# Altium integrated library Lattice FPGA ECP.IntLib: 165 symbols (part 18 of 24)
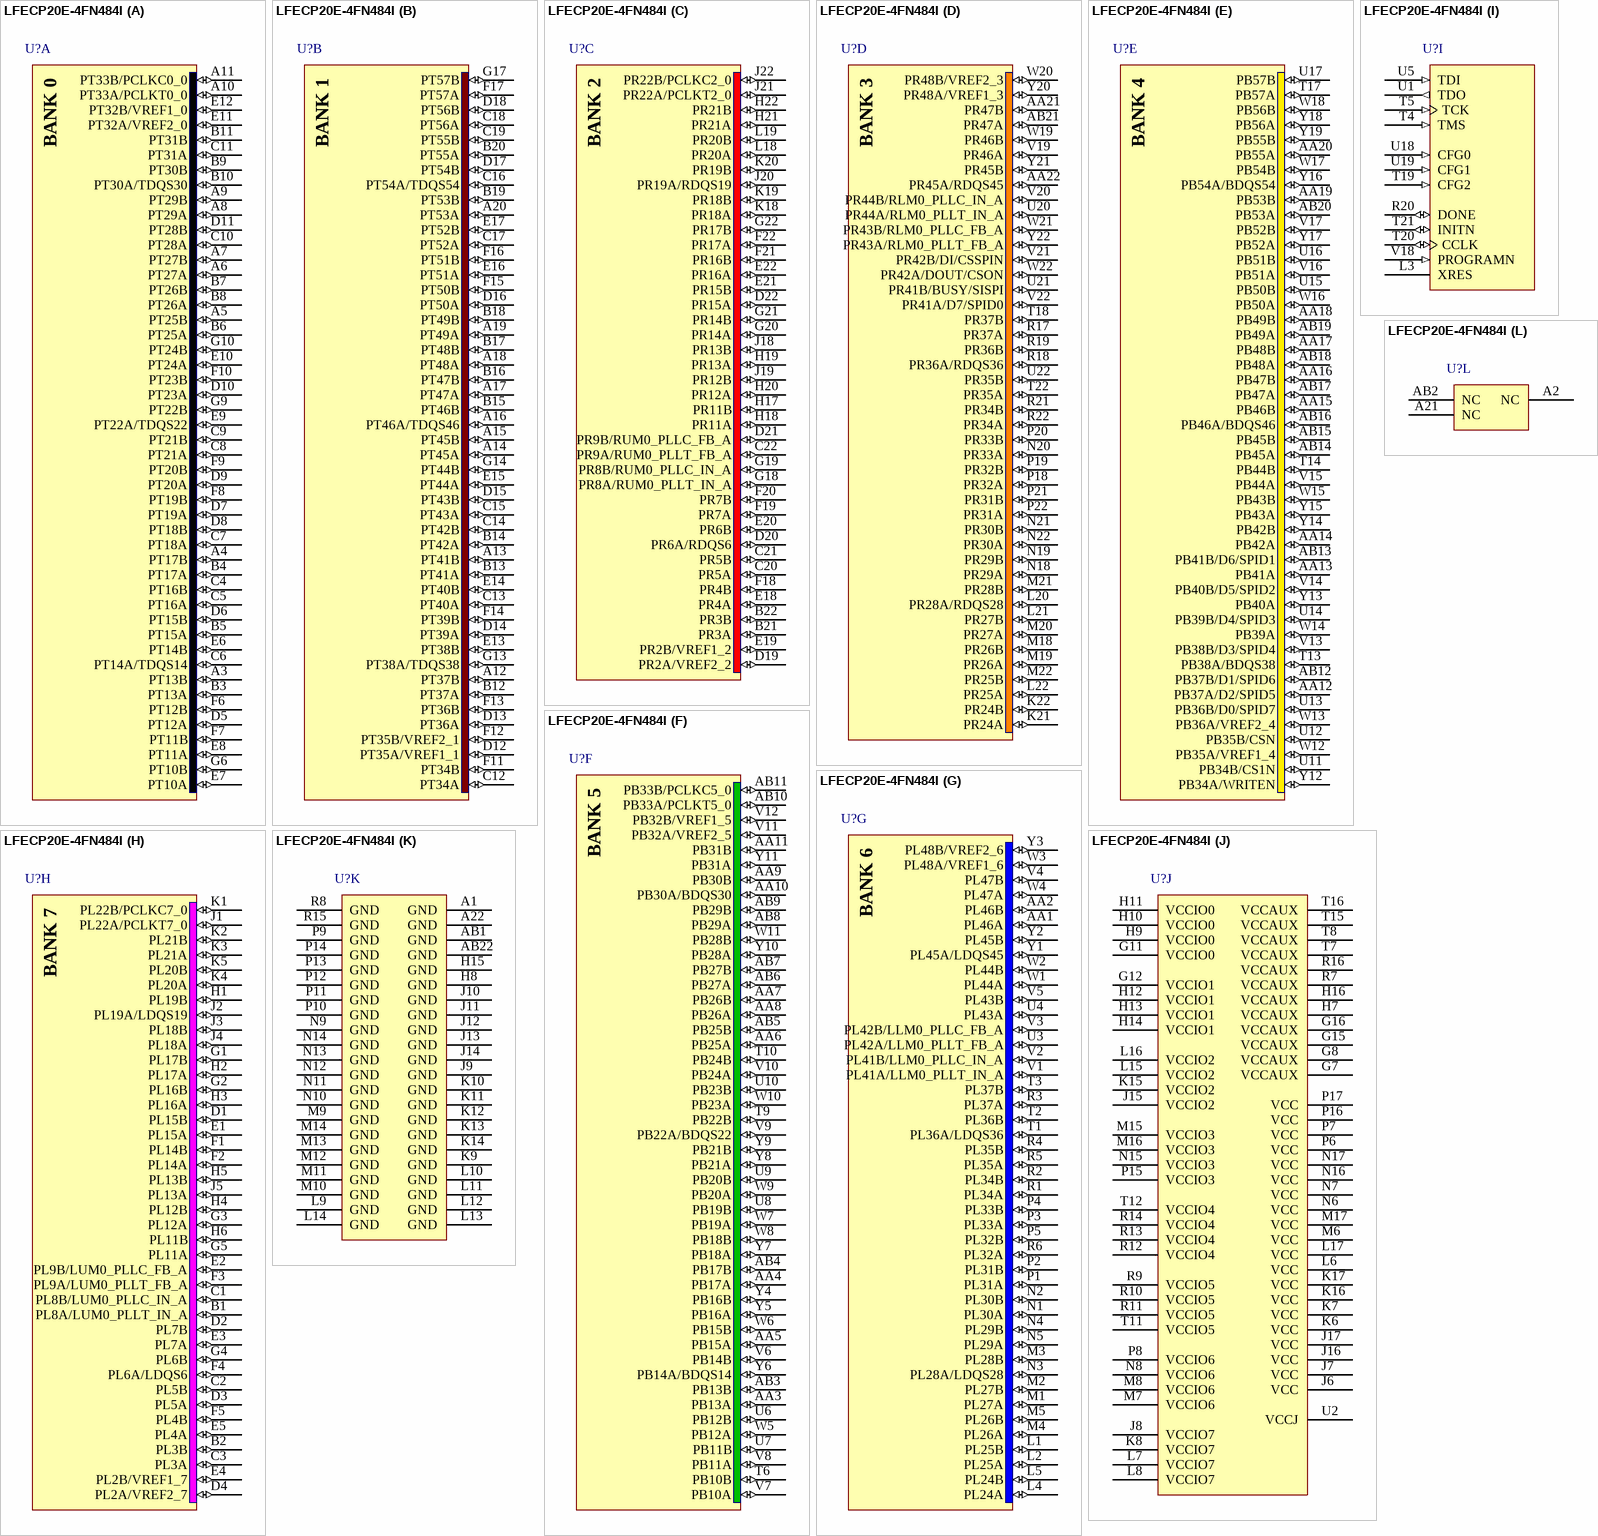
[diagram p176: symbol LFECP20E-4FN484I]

## LFECP20E-4FN484I
designator U?
ECP 1.2V FPGA, 360 I/Os, 4 PLLs, 19.7K LUTs, 7 sysDSP Blocks, 28 18x18 Multipliers, 484-Pin fpBGA, Pb-Free, Speed Grade 4, Industrial Temperature Grade; Note: Pins J6, J17, P6 and P17 are tied to VCCPLL.
footprint fpBGA484 (BGA, 484-Leads, Body 23x23mm, Pitch 1mm)
3D model ECP20E-fpBGA484 (484-Ball Fine Pitch Ball Grid Array (fpBGA484))
part A pins: A3 PT13B (io), A4 PT17B (io), A5 PT25B (io), A6 PT27A (io), A7 PT27B (io), A8 PT29A (io), A9 PT29B (io), A10 PT33A/PCLKT0_0 (io), A11 PT33B/PCLKC0_0 (io), B3 PT13A (io), B4 PT17A (io), B5 PT15A (io), B6 PT25A (io), B7 PT26B (io), B8 PT26A (io), B9 PT30B (io), B10 PT30A/TDQS30 (io), B11 PT31B (io), C4 PT16B (io), C5 PT16A (io), C6 PT14A/TDQS14 (io), C7 PT18A (io), C8 PT21A (io), C9 PT21B (io), C10 PT28A (io), C11 PT31A (io), D5 PT12A (io), D6 PT15B (io), D7 PT19A (io), D8 PT18B (io), D9 PT20A (io), D10 PT23A (io), D11 PT28B (io), E6 PT14B (io), E7 PT10A (io), E8 PT11A (io), E9 PT22A/TDQS22 (io), E10 PT24A (io), E11 PT32A/VREF2_0 (io), E12 PT32B/VREF1_0 (io), F6 PT12B (io), F7 PT11B (io), F8 PT19B (io), F9 PT20B (io), F10 PT23B (io), G6 PT10B (io), G9 PT22B (io), G10 PT24B (io)
part B pins: A12 PT37B (io), A13 PT41B (io), A14 PT45A (io), A15 PT45B (io), A16 PT46A/TDQS46 (io), A17 PT47A (io), A18 PT48A (io), A19 PT49A (io), A20 PT53A (io), B12 PT37A (io), B13 PT41A (io), B14 PT42A (io), B15 PT46B (io), B16 PT47B (io), B17 PT48B (io), B18 PT49B (io), B19 PT53B (io), B20 PT55A (io), C12 PT34A (io), C13 PT40A (io), C14 PT42B (io), C15 PT43A (io), C16 PT54A/TDQS54 (io), C17 PT52A (io), C18 PT56A (io), C19 PT55B (io), D12 PT35A/VREF1_1 (io), D13 PT36A (io), D14 PT39A (io), D15 PT43B (io), D16 PT50A (io), D17 PT54B (io), D18 PT56B (io), E13 PT38B (io), E14 PT40B (io), E15 PT44A (io), E16 PT51A (io), E17 PT52B (io), F11 PT34B (io), F12 PT35B/VREF2_1 (io), F13 PT36B (io), F14 PT39B (io), F15 PT50B (io), F16 PT51B (io), F17 PT57A (io), G13 PT38A/TDQS38 (io), G14 PT44B (io), G17 PT57B (io)
part C pins: B21 PR3A (io), B22 PR3B (io), C20 PR5A (io), C21 PR5B (io), C22 PR9A/RUM0_PLLT_FB_A (io), D19 PR2A/VREF2_2 (io), D20 PR6A/RDQS6 (io), D21 PR9B/RUM0_PLLC_FB_A (io), D22 PR15A (io), E18 PR4A (io), E19 PR2B/VREF1_2 (io), E20 PR6B (io), E21 PR15B (io), E22 PR16A (io), F18 PR4B (io), F19 PR7A (io), F20 PR7B (io), F21 PR16B (io), F22 PR17A (io), G18 PR8A/RUM0_PLLT_IN_A (io), G19 PR8B/RUM0_PLLC_IN_A (io), G20 PR14A (io), G21 PR14B (io), G22 PR17B (io), H17 PR11B (io), H18 PR11A (io), H19 PR13A (io), H20 PR12A (io), H21 PR21A (io), H22 PR21B (io), J18 PR13B (io), J19 PR12B (io), J20 PR19A/RDQS19 (io), J21 PR22A/PCLKT2_0 (io), J22 PR22B/PCLKC2_0 (io), K18 PR18A (io), K19 PR18B (io), K20 PR19B (io), L18 PR20A (io), L19 PR20B (io)
part D pins: AA21 PR47B (io), AA22 PR45A/RDQS45 (io), AB21 PR47A (io), K21 PR24A (io), K22 PR24B (io), L20 PR28A/RDQS28 (io), L21 PR27B (io), L22 PR25A (io), M18 PR26B (io), M19 PR26A (io), M20 PR27A (io), M21 PR28B (io), M22 PR25B (io), N18 PR29A (io), N19 PR29B (io), N20 PR33A (io), N21 PR30B (io), N22 PR30A (io), P18 PR32A (io), P19 PR32B (io), P20 PR33B (io), P21 PR31B (io), P22 PR31A (io), R17 PR37A (io), R18 PR36A/RDQS36 (io), R19 PR36B (io), R21 PR34B (io), R22 PR34A (io), T18 PR37B (io), T22 PR35A (io), U20 PR44A/RLM0_PLLT_IN_A (io), U21 PR41B/BUSY/SISPI (io), U22 PR35B (io), V19 PR46A (io), V20 PR44B/RLM0_PLLC_IN_A (io), V21 PR42B/DI/CSSPIN (io), V22 PR41A/D7/SPID0 (io), W19 PR46B (io), W20 PR48B/VREF2_3 (io), W21 PR43B/RLM0_PLLC_FB_A (io), W22 PR42A/DOUT/CSON (io), Y20 PR48A/VREF1_3 (io), Y21 PR45B (io), Y22 PR43A/RLM0_PLLT_FB_A (io)
part E pins: AA12 PB37A/D2/SPID5 (io), AA13 PB41A (io), AA14 PB42A (io), AA15 PB46B (io), AA16 PB47B (io), AA17 PB48B (io), AA18 PB49B (io), AA19 PB53B (io), AA20 PB55A (io), AB12 PB37B/D1/SPID6 (io), AB13 PB41B/D6/SPID1 (io), AB14 PB45A (io), AB15 PB45B (io), AB16 PB46A/BDQS46 (io), AB17 PB47A (io), AB18 PB48A (io), AB19 PB49A (io), AB20 PB53A (io), T13 PB38A/BDQS38 (io), T14 PB44B (io), T17 PB57A (io), U11 PB34B/CS1N (io), U12 PB35B/CSN (io), U13 PB36B/D0/SPID7 (io), U14 PB39B/D4/SPID3 (io), U15 PB50B (io), U16 PB51B (io), U17 PB57B (io), V13 PB38B/D3/SPID4 (io), V14 PB40B/D5/SPID2 (io), V15 PB44A (io), V16 PB51A (io), V17 PB52B (io), W12 PB35A/VREF1_4 (io), W13 PB36A/VREF2_4 (io), W14 PB39A (io), W15 PB43B (io), W16 PB50A (io), W17 PB54B (io), W18 PB56B (io), Y12 PB34A/WRITEN (io), Y13 PB40A (io), Y14 PB42B (io), Y15 PB43A (io), Y16 PB54A/BDQS54 (io), Y17 PB52A (io), Y18 PB56A (io), Y19 PB55B (io)
part F pins: AA3 PB13A (io), AA4 PB17A (io), AA5 PB15A (io), AA6 PB25A (io), AA7 PB26B (io), AA8 PB26A (io), AA9 PB30B (io), AA10 PB30A/BDQS30 (io), AA11 PB31B (io), AB3 PB13B (io), AB4 PB17B (io), AB5 PB25B (io), AB6 PB27A (io), AB7 PB27B (io), AB8 PB29A (io), AB9 PB29B (io), AB10 PB33A/PCLKT5_0 (io), AB11 PB33B/PCLKC5_0 (io), T6 PB10B (io), T9 PB22B (io), T10 PB24B (io), U6 PB12B (io), U7 PB11B (io), U8 PB19B (io), U9 PB20B (io), U10 PB23B (io), V6 PB14B (io), V7 PB10A (io), V8 PB11A (io), V9 PB22A/BDQS22 (io), V10 PB24A (io), V11 PB32A/VREF2_5 (io), V12 PB32B/VREF1_5 (io), W5 PB12A (io), W6 PB15B (io), W7 PB19A (io), W8 PB18B (io), W9 PB20A (io), W10 PB23A (io), W11 PB28B (io), Y4 PB16B (io), Y5 PB16A (io), Y6 PB14A/BDQS14 (io), Y7 PB18A (io), Y8 PB21A (io), Y9 PB21B (io), Y10 PB28A (io), Y11 PB31A (io)
part G pins: AA1 PL46A (io), AA2 PL46B (io), L1 PL25B (io), L2 PL25A (io), L4 PL24A (io), L5 PL24B (io), M1 PL27A (io), M2 PL27B (io), M3 PL28B (io), M4 PL26A (io), M5 PL26B (io), N1 PL30A (io), N2 PL30B (io), N3 PL28A/LDQS28 (io), N4 PL29B (io), N5 PL29A (io), P1 PL31A (io), P2 PL31B (io), P3 PL33A (io), P4 PL33B (io), P5 PL32B (io), R1 PL34A (io), R2 PL34B (io), R3 PL37A (io), R4 PL35B (io), R5 PL35A (io), R6 PL32A (io), T1 PL36A/LDQS36 (io), T2 PL36B (io), T3 PL37B (io), U3 PL42A/LLM0_PLLT_FB_A (io), U4 PL43A (io), V1 PL41A/LLM0_PLLT_IN_A (io), V2 PL41B/LLM0_PLLC_IN_A (io), V3 PL42B/LLM0_PLLC_FB_A (io), V4 PL47B (io), V5 PL43B (io), W1 PL44A (io), W2 PL44B (io), W3 PL48A/VREF1_6 (io), W4 PL47A (io), Y1 PL45A/LDQS45 (io), Y2 PL45B (io), Y3 PL48B/VREF2_6 (io)
part H pins: B1 PL8A/LUM0_PLLT_IN_A (io), B2 PL3B (io), C1 PL8B/LUM0_PLLC_IN_A (io), C2 PL5B (io), C3 PL3A (io), D1 PL15B (io), D2 PL7B (io), D3 PL5A (io), D4 PL2A/VREF2_7 (io), E1 PL15A (io), E2 PL9B/LUM0_PLLC_FB_A (io), E3 PL7A (io), E4 PL2B/VREF1_7 (io), E5 PL4A (io), F1 PL14B (io), F2 PL14A (io), F3 PL9A/LUM0_PLLT_FB_A (io), F4 PL6A/LDQS6 (io), F5 PL4B (io), G1 PL17B (io), G2 PL16B (io), G3 PL12A (io), G4 PL6B (io), G5 PL11A (io), H1 PL19B (io), H2 PL17A (io), H3 PL16A (io), H4 PL12B (io), H5 PL13B (io), H6 PL11B (io), J1 PL22A/PCLKT7_0 (io), J2 PL19A/LDQS19 (io), J3 PL18B (io), J4 PL18A (io), J5 PL13A (io), K1 PL22B/PCLKC7_0 (io), K2 PL21B (io), K3 PL21A (io), K4 PL20A (io), K5 PL20B (io)
part I pins: L3 XRES, R20 DONE (io), T4 TMS (in), T5 TCK (in), T19 CFG2 (in), T20 CCLK (io), T21 INITN (io), U1 TDO (out), U5 TDI (in), U18 CFG0 (in), U19 CFG1 (in), V18 PROGRAMN (in)
part J pins: G7 VCCAUX (power), G8 VCCAUX (power), G11 VCCIO0 (power), G12 VCCIO1 (power), G15 VCCAUX (power), G16 VCCAUX (power), H7 VCCAUX (power), H9 VCCIO0 (power), H10 VCCIO0 (power), H11 VCCIO0 (power), H12 VCCIO1 (power), H13 VCCIO1 (power), H14 VCCIO1 (power), H16 VCCAUX (power), J6 VCC (power), J7 VCC (power), J8 VCCIO7 (power), J15 VCCIO2 (power), J16 VCC (power), J17 VCC (power), K6 VCC (power), K7 VCC (power), K8 VCCIO7 (power), K15 VCCIO2 (power), K16 VCC (power), K17 VCC (power), L6 VCC (power), L7 VCCIO7 (power), L8 VCCIO7 (power), L15 VCCIO2 (power), L16 VCCIO2 (power), L17 VCC (power), M6 VCC (power), M7 VCCIO6 (power), M8 VCCIO6 (power), M15 VCCIO3 (power), M16 VCCIO3 (power), M17 VCC (power), N6 VCC (power), N7 VCC (power), N8 VCCIO6 (power), N15 VCCIO3 (power), N16 VCC (power), N17 VCC (power), P6 VCC (power), P7 VCC (power), P8 VCCIO6 (power), P15 VCCIO3 (power), P16 VCC (power), P17 VCC (power), R7 VCCAUX (power), R9 VCCIO5 (power), R10 VCCIO5 (power), R11 VCCIO5 (power), R12 VCCIO4 (power), R13 VCCIO4 (power), R14 VCCIO4 (power), R16 VCCAUX (power), T7 VCCAUX (power), T8 VCCAUX (power), T11 VCCIO5 (power), T12 VCCIO4 (power), T15 VCCAUX (power), T16 VCCAUX (power), U2 VCCJ (power)
part K pins: A1 GND (power), A22 GND (power), AB1 GND (power), AB22 GND (power), H8 GND (power), H15 GND (power), J9 GND (power), J10 GND (power), J11 GND (power), J12 GND (power), J13 GND (power), J14 GND (power), K9 GND (power), K10 GND (power), K11 GND (power), K12 GND (power), K13 GND (power), K14 GND (power), L9 GND (power), L10 GND (power), L11 GND (power), L12 GND (power), L13 GND (power), L14 GND (power), M9 GND (power), M10 GND (power), M11 GND (power), M12 GND (power), M13 GND (power), M14 GND (power), N9 GND (power), N10 GND (power), N11 GND (power), N12 GND (power), N13 GND (power), N14 GND (power), P9 GND (power), P10 GND (power), P11 GND (power), P12 GND (power), P13 GND (power), P14 GND (power), R8 GND (power), R15 GND (power)
part L pins: A2 NC, A21 NC, AB2 NC

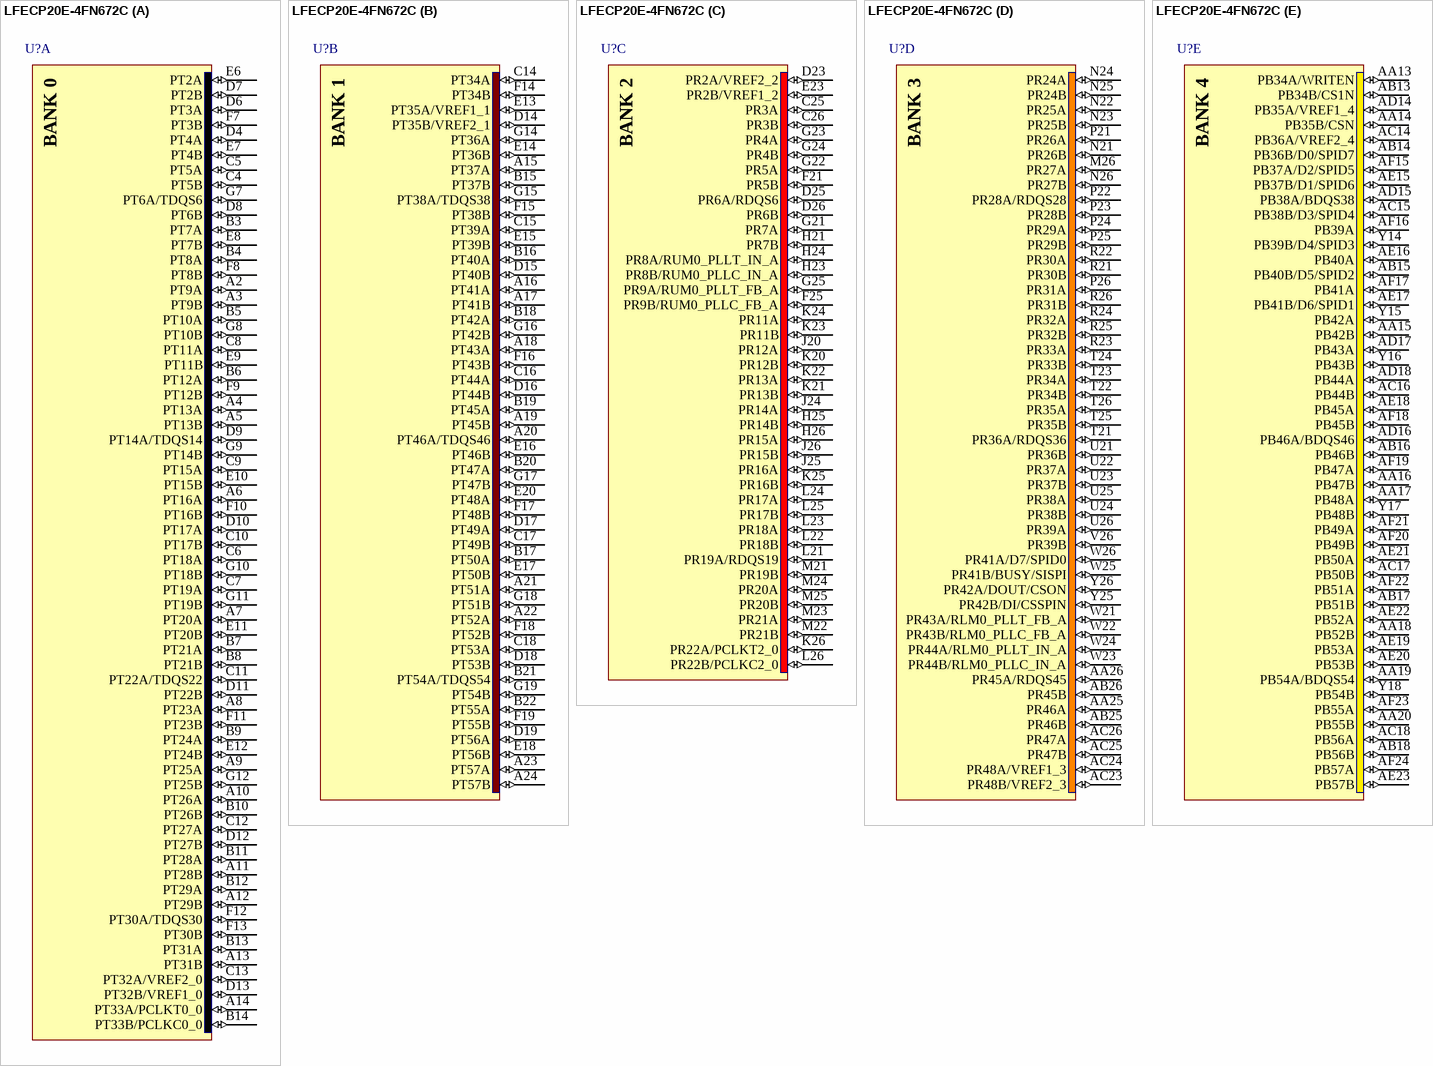
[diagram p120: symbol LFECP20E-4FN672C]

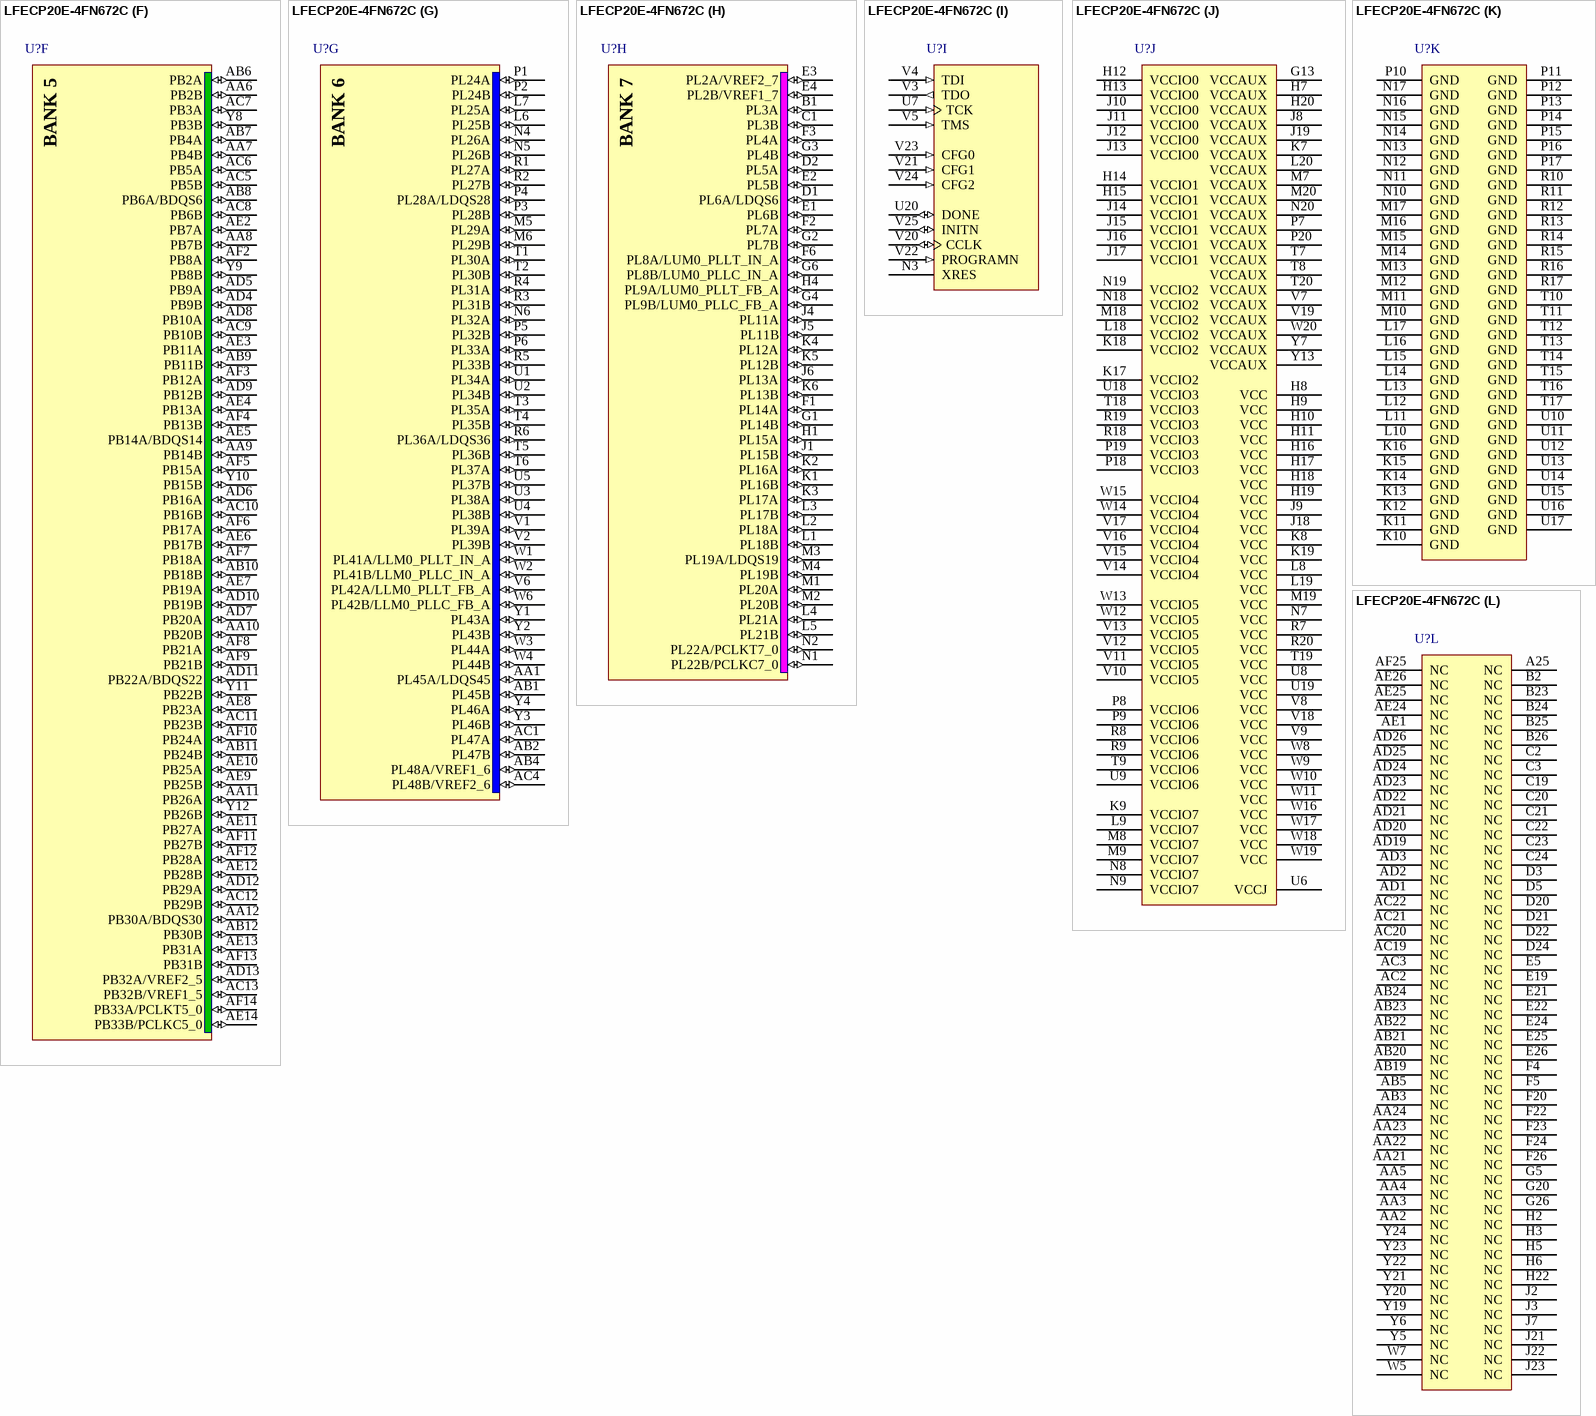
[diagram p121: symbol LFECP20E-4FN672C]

## LFECP20E-4FN672C
designator U?
ECP 1.2V FPGA, 400 I/Os, 4 PLLs, 19.7K LUTs, 7 sysDSP Blocks, 28 18x18 Multipliers, 672-Pin fpBGA, Pb-Free, Speed Grade 4, Commercial Temperature Grade; Note: Pins K19, L8, U8 and U19 are tied to VCCPLL.
footprint fpBGA672 (BGA, 672-Leads, Body 27x27mm, Pitch 1mm)
3D model ECP20E-fpBGA672 (672-Ball Fine Pitch Ball Grid Array (fpBGA672))
part A pins: A2 PT9A (io), A3 PT9B (io), A4 PT13A (io), A5 PT13B (io), A6 PT16A (io), A7 PT20A (io), A8 PT23A (io), A9 PT25A (io), A10 PT26A (io), A11 PT28B (io), A12 PT29B (io), A13 PT31B (io), A14 PT33A/PCLKT0_0 (io), B3 PT7A (io), B4 PT8A (io), B5 PT10A (io), B6 PT12A (io), B7 PT21A (io), B8 PT21B (io), B9 PT24A (io), B10 PT26B (io), B11 PT28A (io), B12 PT29A (io), B13 PT31A (io), B14 PT33B/PCLKC0_0 (io), C4 PT5B (io), C5 PT5A (io), C6 PT18A (io), C7 PT19A (io), C8 PT11A (io), C9 PT15A (io), C10 PT17B (io), C11 PT22A/TDQS22 (io), C12 PT27A (io), C13 PT32A/VREF2_0 (io), D4 PT4A (io), D6 PT3A (io), D7 PT2B (io), D8 PT6B (io), D9 PT14A/TDQS14 (io), D10 PT17A (io), D11 PT22B (io), D12 PT27B (io), D13 PT32B/VREF1_0 (io), E6 PT2A (io), E7 PT4B (io), E8 PT7B (io), E9 PT11B (io), E10 PT15B (io), E11 PT20B (io), E12 PT24B (io), F7 PT3B (io), F8 PT8B (io), F9 PT12B (io), F10 PT16B (io), F11 PT23B (io), F12 PT30A/TDQS30 (io), F13 PT30B (io), G7 PT6A/TDQS6 (io), G8 PT10B (io), G9 PT14B (io), G10 PT18B (io), G11 PT19B (io), G12 PT25B (io)
part B pins: A15 PT37A (io), A16 PT41A (io), A17 PT41B (io), A18 PT43A (io), A19 PT45B (io), A20 PT46A/TDQS46 (io), A21 PT51A (io), A22 PT52A (io), A23 PT57A (io), A24 PT57B (io), B15 PT37B (io), B16 PT40A (io), B17 PT50A (io), B18 PT42A (io), B19 PT45A (io), B20 PT47A (io), B21 PT54A/TDQS54 (io), B22 PT55A (io), C14 PT34A (io), C15 PT39A (io), C16 PT44A (io), C17 PT49B (io), C18 PT53A (io), D14 PT35B/VREF2_1 (io), D15 PT40B (io), D16 PT44B (io), D17 PT49A (io), D18 PT53B (io), D19 PT56A (io), E13 PT35A/VREF1_1 (io), E14 PT36B (io), E15 PT39B (io), E16 PT46B (io), E17 PT50B (io), E18 PT56B (io), E20 PT48A (io), F14 PT34B (io), F15 PT38B (io), F16 PT43B (io), F17 PT48B (io), F18 PT52B (io), F19 PT55B (io), G14 PT36A (io), G15 PT38A/TDQS38 (io), G16 PT42B (io), G17 PT47B (io), G18 PT51B (io), G19 PT54B (io)
part C pins: C25 PR3A (io), C26 PR3B (io), D23 PR2A/VREF2_2 (io), D25 PR6A/RDQS6 (io), D26 PR6B (io), E23 PR2B/VREF1_2 (io), F21 PR5B (io), F25 PR9B/RUM0_PLLC_FB_A (io), G21 PR7A (io), G22 PR5A (io), G23 PR4A (io), G24 PR4B (io), G25 PR9A/RUM0_PLLT_FB_A (io), H21 PR7B (io), H23 PR8B/RUM0_PLLC_IN_A (io), H24 PR8A/RUM0_PLLT_IN_A (io), H25 PR14B (io), H26 PR15A (io), J20 PR12A (io), J24 PR14A (io), J25 PR16A (io), J26 PR15B (io), K20 PR12B (io), K21 PR13B (io), K22 PR13A (io), K23 PR11B (io), K24 PR11A (io), K25 PR16B (io), K26 PR22A/PCLKT2_0 (io), L21 PR19A/RDQS19 (io), L22 PR18B (io), L23 PR18A (io), L24 PR17A (io), L25 PR17B (io), L26 PR22B/PCLKC2_0 (io), M21 PR19B (io), M22 PR21B (io), M23 PR21A (io), M24 PR20A (io), M25 PR20B (io)
part D pins: AA25 PR46A (io), AA26 PR45A/RDQS45 (io), AB25 PR46B (io), AB26 PR45B (io), AC23 PR48B/VREF2_3 (io), AC24 PR48A/VREF1_3 (io), AC25 PR47B (io), AC26 PR47A (io), M26 PR27A (io), N21 PR26B (io), N22 PR25A (io), N23 PR25B (io), N24 PR24A (io), N25 PR24B (io), N26 PR27B (io), P21 PR26A (io), P22 PR28A/RDQS28 (io), P23 PR28B (io), P24 PR29A (io), P25 PR29B (io), P26 PR31A (io), R21 PR30B (io), R22 PR30A (io), R23 PR33A (io), R24 PR32A (io), R25 PR32B (io), R26 PR31B (io), T21 PR36A/RDQS36 (io), T22 PR34B (io), T23 PR34A (io), T24 PR33B (io), T25 PR35B (io), T26 PR35A (io), U21 PR36B (io), U22 PR37A (io), U23 PR37B (io), U24 PR38B (io), U25 PR38A (io), U26 PR39A (io), V26 PR39B (io), W21 PR43A/RLM0_PLLT_FB_A (io), W22 PR43B/RLM0_PLLC_FB_A (io), W23 PR44B/RLM0_PLLC_IN_A (io), W24 PR44A/RLM0_PLLT_IN_A (io), W25 PR41B/BUSY/SISPI (io), W26 PR41A/D7/SPID0 (io), Y25 PR42B/DI/CSSPIN (io), Y26 PR42A/DOUT/CSON (io)
part E pins: AA13 PB34A/WRITEN (io), AA14 PB35B/CSN (io), AA15 PB42B (io), AA16 PB47B (io), AA17 PB48A (io), AA18 PB52B (io), AA19 PB54A/BDQS54 (io), AA20 PB55B (io), AB13 PB34B/CS1N (io), AB14 PB36B/D0/SPID7 (io), AB15 PB40B/D5/SPID2 (io), AB16 PB46B (io), AB17 PB51B (io), AB18 PB56B (io), AC14 PB36A/VREF2_4 (io), AC15 PB38B/D3/SPID4 (io), AC16 PB44B (io), AC17 PB50B (io), AC18 PB56A (io), AD14 PB35A/VREF1_4 (io), AD15 PB38A/BDQS38 (io), AD16 PB46A/BDQS46 (io), AD17 PB43A (io), AD18 PB44A (io), AE15 PB37B/D1/SPID6 (io), AE16 PB40A (io), AE17 PB41B/D6/SPID1 (io), AE18 PB45A (io), AE19 PB53A (io), AE20 PB53B (io), AE21 PB50A (io), AE22 PB52A (io), AE23 PB57B (io), AF15 PB37A/D2/SPID5 (io), AF16 PB39A (io), AF17 PB41A (io), AF18 PB45B (io), AF19 PB47A (io), AF20 PB49B (io), AF21 PB49A (io), AF22 PB51A (io), AF23 PB55A (io), AF24 PB57A (io), Y14 PB39B/D4/SPID3 (io), Y15 PB42A (io), Y16 PB43B (io), Y17 PB48B (io), Y18 PB54B (io)
part F pins: AA6 PB2B (io), AA7 PB4B (io), AA8 PB7B (io), AA9 PB14B (io), AA10 PB20B (io), AA11 PB26A (io), AA12 PB30A/BDQS30 (io), AB6 PB2A (io), AB7 PB4A (io), AB8 PB6A/BDQS6 (io), AB9 PB11B (io), AB10 PB18B (io), AB11 PB24B (io), AB12 PB30B (io), AC5 PB5B (io), AC6 PB5A (io), AC7 PB3A (io), AC8 PB6B (io), AC9 PB10B (io), AC10 PB16B (io), AC11 PB23B (io), AC12 PB29B (io), AC13 PB32B/VREF1_5 (io), AD4 PB9B (io), AD5 PB9A (io), AD6 PB16A (io), AD7 PB20A (io), AD8 PB10A (io), AD9 PB12B (io), AD10 PB19B (io), AD11 PB22A/BDQS22 (io), AD12 PB29A (io), AD13 PB32A/VREF2_5 (io), AE2 PB7A (io), AE3 PB11A (io), AE4 PB13A (io), AE5 PB14A/BDQS14 (io), AE6 PB17B (io), AE7 PB19A (io), AE8 PB23A (io), AE9 PB25B (io), AE10 PB25A (io), AE11 PB27A (io), AE12 PB28B (io), AE13 PB31A (io), AE14 PB33B/PCLKC5_0 (io), AF2 PB8A (io), AF3 PB12A (io), AF4 PB13B (io), AF5 PB15A (io), AF6 PB17A (io), AF7 PB18A (io), AF8 PB21A (io), AF9 PB21B (io), AF10 PB24A (io), AF11 PB27B (io), AF12 PB28A (io), AF13 PB31B (io), AF14 PB33A/PCLKT5_0 (io), Y8 PB3B (io), Y9 PB8B (io), Y10 PB15B (io), Y11 PB22B (io), Y12 PB26B (io)
part G pins: AA1 PL45A/LDQS45 (io), AB1 PL45B (io), AB2 PL47B (io), AB4 PL48A/VREF1_6 (io), AC1 PL47A (io), AC4 PL48B/VREF2_6 (io), L6 PL25B (io), L7 PL25A (io), M5 PL29A (io), M6 PL29B (io), N4 PL26A (io), N5 PL26B (io), N6 PL32A (io), P1 PL24A (io), P2 PL24B (io), P3 PL28B (io), P4 PL28A/LDQS28 (io), P5 PL32B (io), P6 PL33A (io), R1 PL27A (io), R2 PL27B (io), R3 PL31B (io), R4 PL31A (io), R5 PL33B (io), R6 PL36A/LDQS36 (io), T1 PL30A (io), T2 PL30B (io), T3 PL35A (io), T4 PL35B (io), T5 PL36B (io), T6 PL37A (io), U1 PL34A (io), U2 PL34B (io), U3 PL38A (io), U4 PL38B (io), U5 PL37B (io), V1 PL39A (io), V2 PL39B (io), V6 PL42A/LLM0_PLLT_FB_A (io), W1 PL41A/LLM0_PLLT_IN_A (io), W2 PL41B/LLM0_PLLC_IN_A (io), W3 PL44A (io), W4 PL44B (io), W6 PL42B/LLM0_PLLC_FB_A (io), Y1 PL43A (io), Y2 PL43B (io), Y3 PL46B (io), Y4 PL46A (io)
part H pins: B1 PL3A (io), C1 PL3B (io), D1 PL6A/LDQS6 (io), D2 PL5A (io), E1 PL6B (io), E2 PL5B (io), E3 PL2A/VREF2_7 (io), E4 PL2B/VREF1_7 (io), F1 PL14A (io), F2 PL7A (io), F3 PL4A (io), F6 PL8A/LUM0_PLLT_IN_A (io), G1 PL14B (io), G2 PL7B (io), G3 PL4B (io), G4 PL9B/LUM0_PLLC_FB_A (io), G6 PL8B/LUM0_PLLC_IN_A (io), H1 PL15A (io), H4 PL9A/LUM0_PLLT_FB_A (io), J1 PL15B (io), J4 PL11A (io), J5 PL11B (io), J6 PL13A (io), K1 PL16B (io), K2 PL16A (io), K3 PL17A (io), K4 PL12A (io), K5 PL12B (io), K6 PL13B (io), L1 PL18B (io), L2 PL18A (io), L3 PL17B (io), L4 PL21A (io), L5 PL21B (io), M1 PL20A (io), M2 PL20B (io), M3 PL19A/LDQS19 (io), M4 PL19B (io), N1 PL22B/PCLKC7_0 (io), N2 PL22A/PCLKT7_0 (io)
part I pins: N3 XRES, U7 TCK (in), U20 DONE (io), V3 TDO (out), V4 TDI (in), V5 TMS (in), V20 CCLK (io), V21 CFG1 (in), V22 PROGRAMN (in), V23 CFG0 (in), V24 CFG2 (in), V25 INITN (io)
part J pins: G13 VCCAUX (power), H7 VCCAUX (power), H8 VCC (power), H9 VCC (power), H10 VCC (power), H11 VCC (power), H12 VCCIO0 (power), H13 VCCIO0 (power), H14 VCCIO1 (power), H15 VCCIO1 (power), H16 VCC (power), H17 VCC (power), H18 VCC (power), H19 VCC (power), H20 VCCAUX (power), J8 VCCAUX (power), J9 VCC (power), J10 VCCIO0 (power), J11 VCCIO0 (power), J12 VCCIO0 (power), J13 VCCIO0 (power), J14 VCCIO1 (power), J15 VCCIO1 (power), J16 VCCIO1 (power), J17 VCCIO1 (power), J18 VCC (power), J19 VCCAUX (power), K7 VCCAUX (power), K8 VCC (power), K9 VCCIO7 (power), K17 VCCIO2 (power), K18 VCCIO2 (power), K19 VCC (power), L8 VCC (power), L9 VCCIO7 (power), L18 VCCIO2 (power), L19 VCC (power), L20 VCCAUX (power), M7 VCCAUX (power), M8 VCCIO7 (power), M9 VCCIO7 (power), M18 VCCIO2 (power), M19 VCC (power), M20 VCCAUX (power), N7 VCC (power), N8 VCCIO7 (power), N9 VCCIO7 (power), N18 VCCIO2 (power), N19 VCCIO2 (power), N20 VCCAUX (power), P7 VCCAUX (power), P8 VCCIO6 (power), P9 VCCIO6 (power), P18 VCCIO3 (power), P19 VCCIO3 (power), P20 VCCAUX (power), R7 VCC (power), R8 VCCIO6 (power), R9 VCCIO6 (power), R18 VCCIO3 (power), R19 VCCIO3 (power), R20 VCC (power), T7 VCCAUX (power), T8 VCCAUX (power), T9 VCCIO6 (power), T18 VCCIO3 (power), T19 VCC (power), T20 VCCAUX (power), U6 VCCJ (power), U8 VCC (power), U9 VCCIO6 (power), U18 VCCIO3 (power), U19 VCC (power), V7 VCCAUX (power), V8 VCC (power), V9 VCC (power), V10 VCCIO5 (power), V11 VCCIO5 (power), V12 VCCIO5 (power), V13 VCCIO5 (power), V14 VCCIO4 (power), V15 VCCIO4 (power), V16 VCCIO4 (power), V17 VCCIO4 (power), V18 VCC (power), V19 VCCAUX (power), W8 VCC (power), W9 VCC (power), W10 VCC (power), W11 VCC (power), W12 VCCIO5 (power), W13 VCCIO5 (power), W14 VCCIO4 (power), W15 VCCIO4 (power), W16 VCC (power), W17 VCC (power), W18 VCC (power), W19 VCC (power), W20 VCCAUX (power), Y7 VCCAUX (power), Y13 VCCAUX (power)
part K pins: K10 GND (power), K11 GND (power), K12 GND (power), K13 GND (power), K14 GND (power), K15 GND (power), K16 GND (power), L10 GND (power), L11 GND (power), L12 GND (power), L13 GND (power), L14 GND (power), L15 GND (power), L16 GND (power), L17 GND (power), M10 GND (power), M11 GND (power), M12 GND (power), M13 GND (power), M14 GND (power), M15 GND (power), M16 GND (power), M17 GND (power), N10 GND (power), N11 GND (power), N12 GND (power), N13 GND (power), N14 GND (power), N15 GND (power), N16 GND (power), N17 GND (power), P10 GND (power), P11 GND (power), P12 GND (power), P13 GND (power), P14 GND (power), P15 GND (power), P16 GND (power), P17 GND (power), R10 GND (power), R11 GND (power), R12 GND (power), R13 GND (power), R14 GND (power), R15 GND (power), R16 GND (power), R17 GND (power), T10 GND (power), T11 GND (power), T12 GND (power), T13 GND (power), T14 GND (power), T15 GND (power), T16 GND (power), T17 GND (power), U10 GND (power), U11 GND (power), U12 GND (power), U13 GND (power), U14 GND (power), U15 GND (power), U16 GND (power), U17 GND (power)
part L pins: A25 NC, AA2 NC, AA3 NC, AA4 NC, AA5 NC, AA21 NC, AA22 NC, AA23 NC, AA24 NC, AB3 NC, AB5 NC, AB19 NC, AB20 NC, AB21 NC, AB22 NC, AB23 NC, AB24 NC, AC2 NC, AC3 NC, AC19 NC, AC20 NC, AC21 NC, AC22 NC, AD1 NC, AD2 NC, AD3 NC, AD19 NC, AD20 NC, AD21 NC, AD22 NC, AD23 NC, AD24 NC, AD25 NC, AD26 NC, AE1 NC, AE24 NC, AE25 NC, AE26 NC, AF25 NC, B2 NC, B23 NC, B24 NC, B25 NC, B26 NC, C2 NC, C3 NC, C19 NC, C20 NC, C21 NC, C22 NC, C23 NC, C24 NC, D3 NC, D5 NC, D20 NC, D21 NC, D22 NC, D24 NC, E5 NC, E19 NC, E21 NC, E22 NC, E24 NC, E25 NC, E26 NC, F4 NC, F5 NC, F20 NC, F22 NC, F23 NC, F24 NC, F26 NC, G5 NC, G20 NC, G26 NC, H2 NC, H3 NC, H5 NC, H6 NC, H22 NC, J2 NC, J3 NC, J7 NC, J21 NC, J22 NC, J23 NC, W5 NC, W7 NC, Y5 NC, Y6 NC, Y19 NC, Y20 NC, Y21 NC, Y22 NC, Y23 NC, Y24 NC

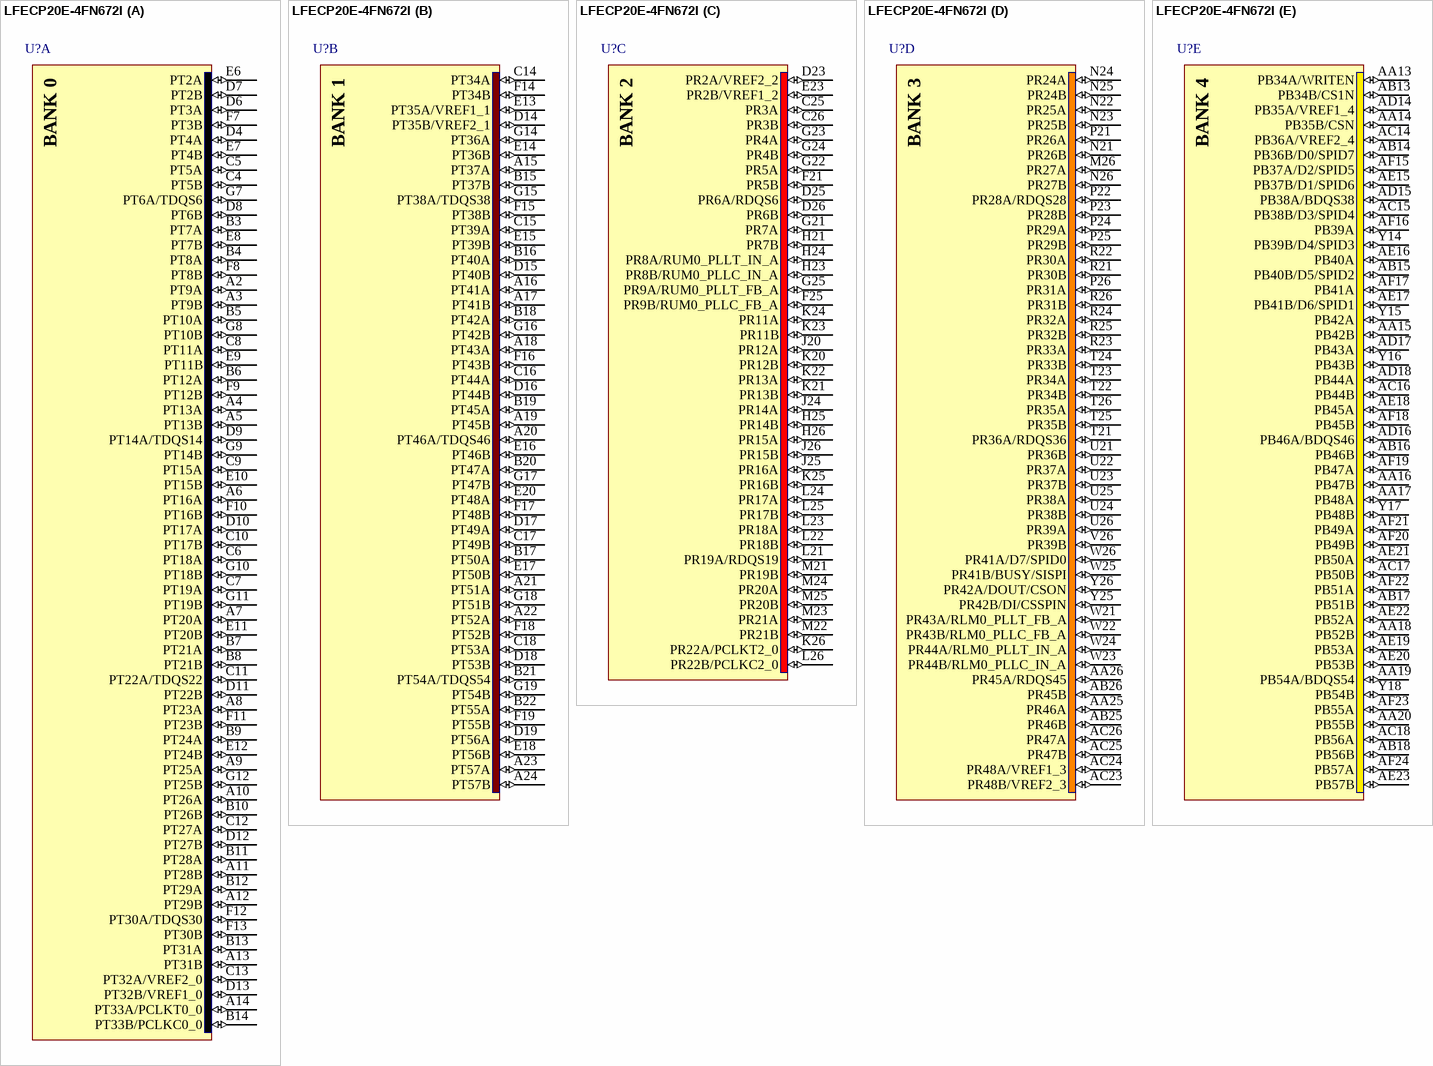
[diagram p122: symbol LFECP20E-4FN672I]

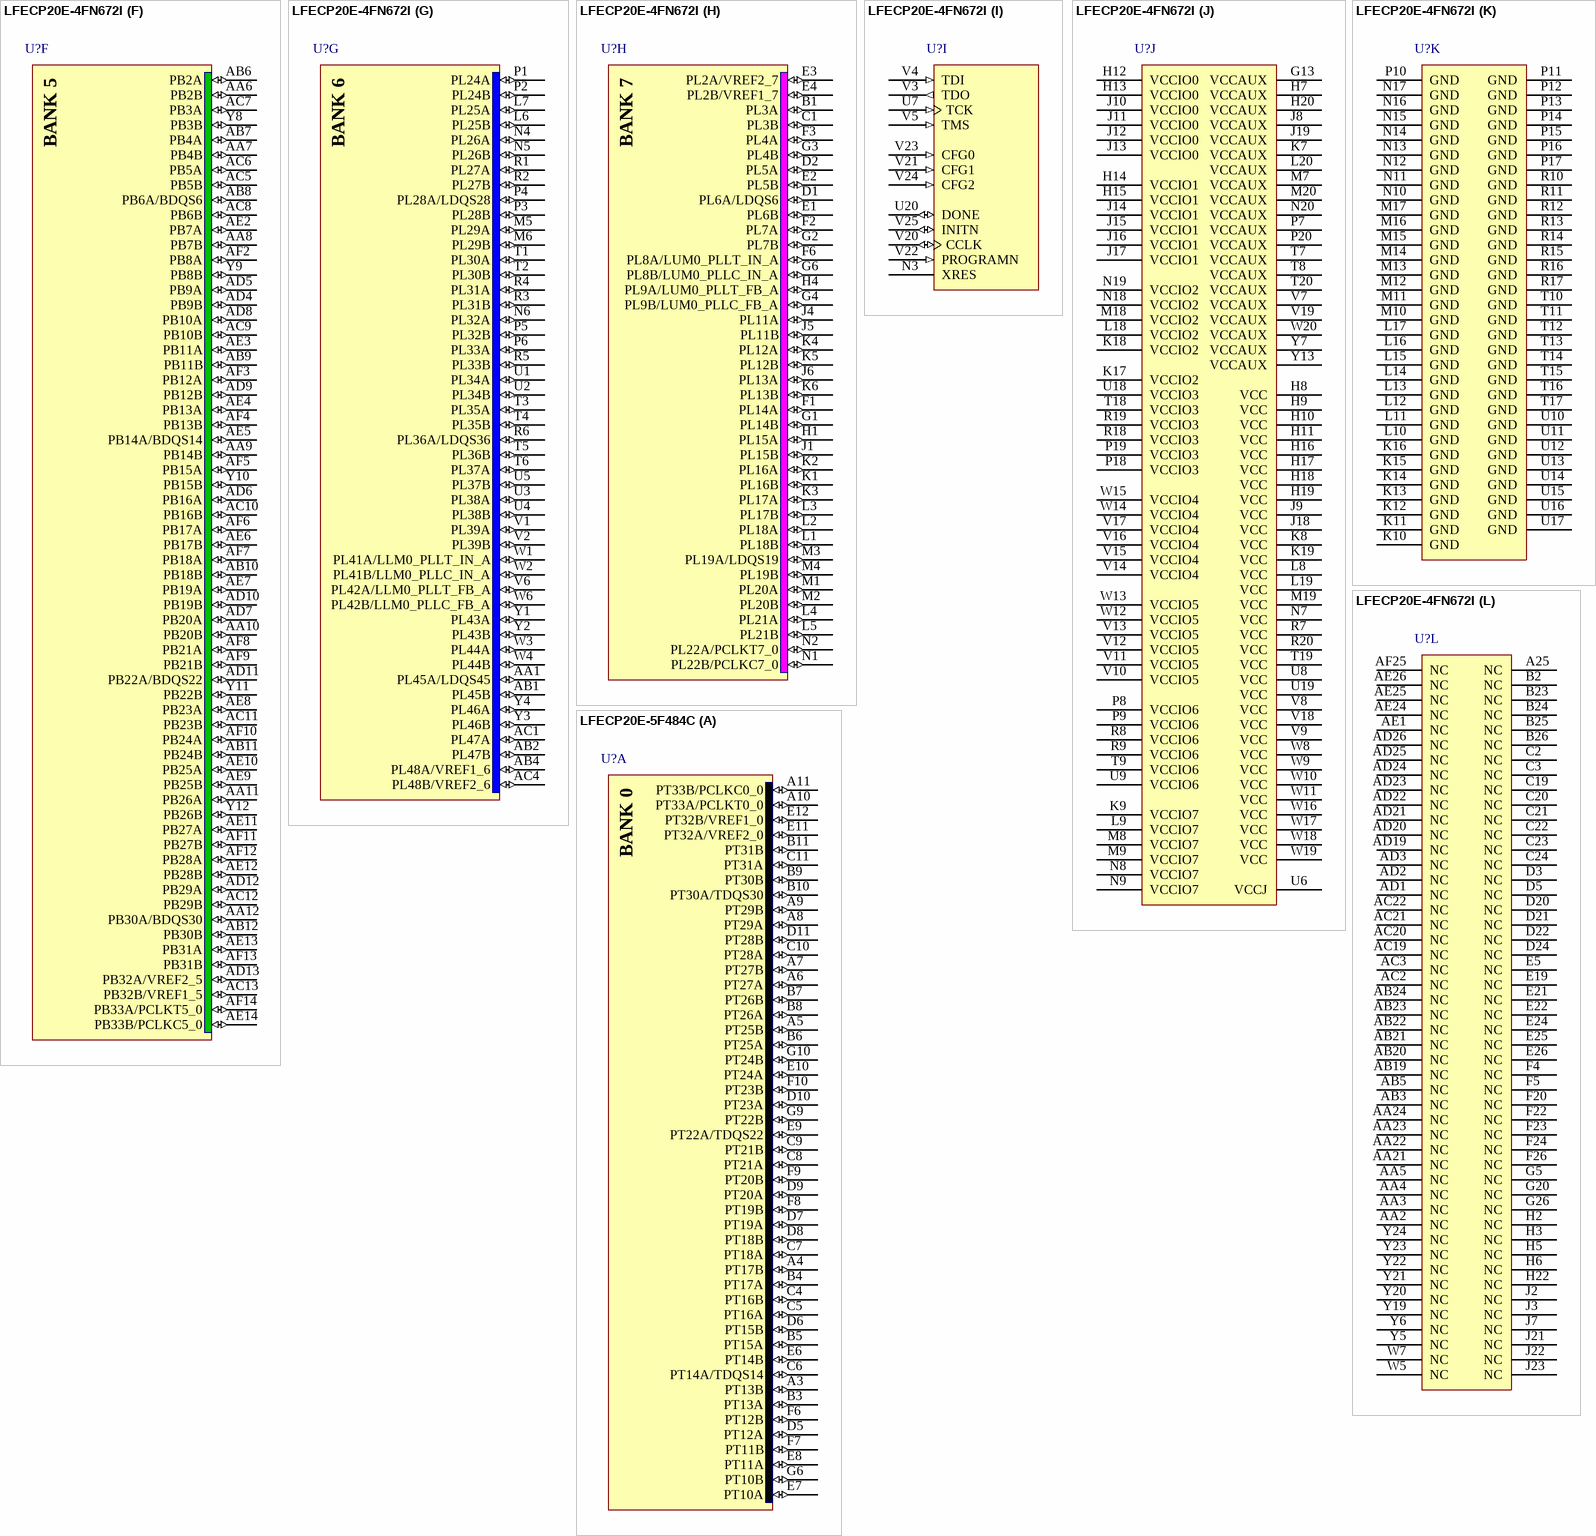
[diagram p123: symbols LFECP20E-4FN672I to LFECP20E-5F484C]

## LFECP20E-4FN672I
designator U?
ECP 1.2V FPGA, 400 I/Os, 4 PLLs, 19.7K LUTs, 7 sysDSP Blocks, 28 18x18 Multipliers, 672-Pin fpBGA, Pb-Free, Speed Grade 4, Industrial Temperature Grade; Note: Pins K19, L8, U8 and U19 are tied to VCCPLL.
footprint fpBGA672 (BGA, 672-Leads, Body 27x27mm, Pitch 1mm)
3D model ECP20E-fpBGA672 (672-Ball Fine Pitch Ball Grid Array (fpBGA672))
part A pins: A2 PT9A (io), A3 PT9B (io), A4 PT13A (io), A5 PT13B (io), A6 PT16A (io), A7 PT20A (io), A8 PT23A (io), A9 PT25A (io), A10 PT26A (io), A11 PT28B (io), A12 PT29B (io), A13 PT31B (io), A14 PT33A/PCLKT0_0 (io), B3 PT7A (io), B4 PT8A (io), B5 PT10A (io), B6 PT12A (io), B7 PT21A (io), B8 PT21B (io), B9 PT24A (io), B10 PT26B (io), B11 PT28A (io), B12 PT29A (io), B13 PT31A (io), B14 PT33B/PCLKC0_0 (io), C4 PT5B (io), C5 PT5A (io), C6 PT18A (io), C7 PT19A (io), C8 PT11A (io), C9 PT15A (io), C10 PT17B (io), C11 PT22A/TDQS22 (io), C12 PT27A (io), C13 PT32A/VREF2_0 (io), D4 PT4A (io), D6 PT3A (io), D7 PT2B (io), D8 PT6B (io), D9 PT14A/TDQS14 (io), D10 PT17A (io), D11 PT22B (io), D12 PT27B (io), D13 PT32B/VREF1_0 (io), E6 PT2A (io), E7 PT4B (io), E8 PT7B (io), E9 PT11B (io), E10 PT15B (io), E11 PT20B (io), E12 PT24B (io), F7 PT3B (io), F8 PT8B (io), F9 PT12B (io), F10 PT16B (io), F11 PT23B (io), F12 PT30A/TDQS30 (io), F13 PT30B (io), G7 PT6A/TDQS6 (io), G8 PT10B (io), G9 PT14B (io), G10 PT18B (io), G11 PT19B (io), G12 PT25B (io)
part B pins: A15 PT37A (io), A16 PT41A (io), A17 PT41B (io), A18 PT43A (io), A19 PT45B (io), A20 PT46A/TDQS46 (io), A21 PT51A (io), A22 PT52A (io), A23 PT57A (io), A24 PT57B (io), B15 PT37B (io), B16 PT40A (io), B17 PT50A (io), B18 PT42A (io), B19 PT45A (io), B20 PT47A (io), B21 PT54A/TDQS54 (io), B22 PT55A (io), C14 PT34A (io), C15 PT39A (io), C16 PT44A (io), C17 PT49B (io), C18 PT53A (io), D14 PT35B/VREF2_1 (io), D15 PT40B (io), D16 PT44B (io), D17 PT49A (io), D18 PT53B (io), D19 PT56A (io), E13 PT35A/VREF1_1 (io), E14 PT36B (io), E15 PT39B (io), E16 PT46B (io), E17 PT50B (io), E18 PT56B (io), E20 PT48A (io), F14 PT34B (io), F15 PT38B (io), F16 PT43B (io), F17 PT48B (io), F18 PT52B (io), F19 PT55B (io), G14 PT36A (io), G15 PT38A/TDQS38 (io), G16 PT42B (io), G17 PT47B (io), G18 PT51B (io), G19 PT54B (io)
part C pins: C25 PR3A (io), C26 PR3B (io), D23 PR2A/VREF2_2 (io), D25 PR6A/RDQS6 (io), D26 PR6B (io), E23 PR2B/VREF1_2 (io), F21 PR5B (io), F25 PR9B/RUM0_PLLC_FB_A (io), G21 PR7A (io), G22 PR5A (io), G23 PR4A (io), G24 PR4B (io), G25 PR9A/RUM0_PLLT_FB_A (io), H21 PR7B (io), H23 PR8B/RUM0_PLLC_IN_A (io), H24 PR8A/RUM0_PLLT_IN_A (io), H25 PR14B (io), H26 PR15A (io), J20 PR12A (io), J24 PR14A (io), J25 PR16A (io), J26 PR15B (io), K20 PR12B (io), K21 PR13B (io), K22 PR13A (io), K23 PR11B (io), K24 PR11A (io), K25 PR16B (io), K26 PR22A/PCLKT2_0 (io), L21 PR19A/RDQS19 (io), L22 PR18B (io), L23 PR18A (io), L24 PR17A (io), L25 PR17B (io), L26 PR22B/PCLKC2_0 (io), M21 PR19B (io), M22 PR21B (io), M23 PR21A (io), M24 PR20A (io), M25 PR20B (io)
part D pins: AA25 PR46A (io), AA26 PR45A/RDQS45 (io), AB25 PR46B (io), AB26 PR45B (io), AC23 PR48B/VREF2_3 (io), AC24 PR48A/VREF1_3 (io), AC25 PR47B (io), AC26 PR47A (io), M26 PR27A (io), N21 PR26B (io), N22 PR25A (io), N23 PR25B (io), N24 PR24A (io), N25 PR24B (io), N26 PR27B (io), P21 PR26A (io), P22 PR28A/RDQS28 (io), P23 PR28B (io), P24 PR29A (io), P25 PR29B (io), P26 PR31A (io), R21 PR30B (io), R22 PR30A (io), R23 PR33A (io), R24 PR32A (io), R25 PR32B (io), R26 PR31B (io), T21 PR36A/RDQS36 (io), T22 PR34B (io), T23 PR34A (io), T24 PR33B (io), T25 PR35B (io), T26 PR35A (io), U21 PR36B (io), U22 PR37A (io), U23 PR37B (io), U24 PR38B (io), U25 PR38A (io), U26 PR39A (io), V26 PR39B (io), W21 PR43A/RLM0_PLLT_FB_A (io), W22 PR43B/RLM0_PLLC_FB_A (io), W23 PR44B/RLM0_PLLC_IN_A (io), W24 PR44A/RLM0_PLLT_IN_A (io), W25 PR41B/BUSY/SISPI (io), W26 PR41A/D7/SPID0 (io), Y25 PR42B/DI/CSSPIN (io), Y26 PR42A/DOUT/CSON (io)
part E pins: AA13 PB34A/WRITEN (io), AA14 PB35B/CSN (io), AA15 PB42B (io), AA16 PB47B (io), AA17 PB48A (io), AA18 PB52B (io), AA19 PB54A/BDQS54 (io), AA20 PB55B (io), AB13 PB34B/CS1N (io), AB14 PB36B/D0/SPID7 (io), AB15 PB40B/D5/SPID2 (io), AB16 PB46B (io), AB17 PB51B (io), AB18 PB56B (io), AC14 PB36A/VREF2_4 (io), AC15 PB38B/D3/SPID4 (io), AC16 PB44B (io), AC17 PB50B (io), AC18 PB56A (io), AD14 PB35A/VREF1_4 (io), AD15 PB38A/BDQS38 (io), AD16 PB46A/BDQS46 (io), AD17 PB43A (io), AD18 PB44A (io), AE15 PB37B/D1/SPID6 (io), AE16 PB40A (io), AE17 PB41B/D6/SPID1 (io), AE18 PB45A (io), AE19 PB53A (io), AE20 PB53B (io), AE21 PB50A (io), AE22 PB52A (io), AE23 PB57B (io), AF15 PB37A/D2/SPID5 (io), AF16 PB39A (io), AF17 PB41A (io), AF18 PB45B (io), AF19 PB47A (io), AF20 PB49B (io), AF21 PB49A (io), AF22 PB51A (io), AF23 PB55A (io), AF24 PB57A (io), Y14 PB39B/D4/SPID3 (io), Y15 PB42A (io), Y16 PB43B (io), Y17 PB48B (io), Y18 PB54B (io)
part F pins: AA6 PB2B (io), AA7 PB4B (io), AA8 PB7B (io), AA9 PB14B (io), AA10 PB20B (io), AA11 PB26A (io), AA12 PB30A/BDQS30 (io), AB6 PB2A (io), AB7 PB4A (io), AB8 PB6A/BDQS6 (io), AB9 PB11B (io), AB10 PB18B (io), AB11 PB24B (io), AB12 PB30B (io), AC5 PB5B (io), AC6 PB5A (io), AC7 PB3A (io), AC8 PB6B (io), AC9 PB10B (io), AC10 PB16B (io), AC11 PB23B (io), AC12 PB29B (io), AC13 PB32B/VREF1_5 (io), AD4 PB9B (io), AD5 PB9A (io), AD6 PB16A (io), AD7 PB20A (io), AD8 PB10A (io), AD9 PB12B (io), AD10 PB19B (io), AD11 PB22A/BDQS22 (io), AD12 PB29A (io), AD13 PB32A/VREF2_5 (io), AE2 PB7A (io), AE3 PB11A (io), AE4 PB13A (io), AE5 PB14A/BDQS14 (io), AE6 PB17B (io), AE7 PB19A (io), AE8 PB23A (io), AE9 PB25B (io), AE10 PB25A (io), AE11 PB27A (io), AE12 PB28B (io), AE13 PB31A (io), AE14 PB33B/PCLKC5_0 (io), AF2 PB8A (io), AF3 PB12A (io), AF4 PB13B (io), AF5 PB15A (io), AF6 PB17A (io), AF7 PB18A (io), AF8 PB21A (io), AF9 PB21B (io), AF10 PB24A (io), AF11 PB27B (io), AF12 PB28A (io), AF13 PB31B (io), AF14 PB33A/PCLKT5_0 (io), Y8 PB3B (io), Y9 PB8B (io), Y10 PB15B (io), Y11 PB22B (io), Y12 PB26B (io)
part G pins: AA1 PL45A/LDQS45 (io), AB1 PL45B (io), AB2 PL47B (io), AB4 PL48A/VREF1_6 (io), AC1 PL47A (io), AC4 PL48B/VREF2_6 (io), L6 PL25B (io), L7 PL25A (io), M5 PL29A (io), M6 PL29B (io), N4 PL26A (io), N5 PL26B (io), N6 PL32A (io), P1 PL24A (io), P2 PL24B (io), P3 PL28B (io), P4 PL28A/LDQS28 (io), P5 PL32B (io), P6 PL33A (io), R1 PL27A (io), R2 PL27B (io), R3 PL31B (io), R4 PL31A (io), R5 PL33B (io), R6 PL36A/LDQS36 (io), T1 PL30A (io), T2 PL30B (io), T3 PL35A (io), T4 PL35B (io), T5 PL36B (io), T6 PL37A (io), U1 PL34A (io), U2 PL34B (io), U3 PL38A (io), U4 PL38B (io), U5 PL37B (io), V1 PL39A (io), V2 PL39B (io), V6 PL42A/LLM0_PLLT_FB_A (io), W1 PL41A/LLM0_PLLT_IN_A (io), W2 PL41B/LLM0_PLLC_IN_A (io), W3 PL44A (io), W4 PL44B (io), W6 PL42B/LLM0_PLLC_FB_A (io), Y1 PL43A (io), Y2 PL43B (io), Y3 PL46B (io), Y4 PL46A (io)
part H pins: B1 PL3A (io), C1 PL3B (io), D1 PL6A/LDQS6 (io), D2 PL5A (io), E1 PL6B (io), E2 PL5B (io), E3 PL2A/VREF2_7 (io), E4 PL2B/VREF1_7 (io), F1 PL14A (io), F2 PL7A (io), F3 PL4A (io), F6 PL8A/LUM0_PLLT_IN_A (io), G1 PL14B (io), G2 PL7B (io), G3 PL4B (io), G4 PL9B/LUM0_PLLC_FB_A (io), G6 PL8B/LUM0_PLLC_IN_A (io), H1 PL15A (io), H4 PL9A/LUM0_PLLT_FB_A (io), J1 PL15B (io), J4 PL11A (io), J5 PL11B (io), J6 PL13A (io), K1 PL16B (io), K2 PL16A (io), K3 PL17A (io), K4 PL12A (io), K5 PL12B (io), K6 PL13B (io), L1 PL18B (io), L2 PL18A (io), L3 PL17B (io), L4 PL21A (io), L5 PL21B (io), M1 PL20A (io), M2 PL20B (io), M3 PL19A/LDQS19 (io), M4 PL19B (io), N1 PL22B/PCLKC7_0 (io), N2 PL22A/PCLKT7_0 (io)
part I pins: N3 XRES, U7 TCK (in), U20 DONE (io), V3 TDO (out), V4 TDI (in), V5 TMS (in), V20 CCLK (io), V21 CFG1 (in), V22 PROGRAMN (in), V23 CFG0 (in), V24 CFG2 (in), V25 INITN (io)
part J pins: G13 VCCAUX (power), H7 VCCAUX (power), H8 VCC (power), H9 VCC (power), H10 VCC (power), H11 VCC (power), H12 VCCIO0 (power), H13 VCCIO0 (power), H14 VCCIO1 (power), H15 VCCIO1 (power), H16 VCC (power), H17 VCC (power), H18 VCC (power), H19 VCC (power), H20 VCCAUX (power), J8 VCCAUX (power), J9 VCC (power), J10 VCCIO0 (power), J11 VCCIO0 (power), J12 VCCIO0 (power), J13 VCCIO0 (power), J14 VCCIO1 (power), J15 VCCIO1 (power), J16 VCCIO1 (power), J17 VCCIO1 (power), J18 VCC (power), J19 VCCAUX (power), K7 VCCAUX (power), K8 VCC (power), K9 VCCIO7 (power), K17 VCCIO2 (power), K18 VCCIO2 (power), K19 VCC (power), L8 VCC (power), L9 VCCIO7 (power), L18 VCCIO2 (power), L19 VCC (power), L20 VCCAUX (power), M7 VCCAUX (power), M8 VCCIO7 (power), M9 VCCIO7 (power), M18 VCCIO2 (power), M19 VCC (power), M20 VCCAUX (power), N7 VCC (power), N8 VCCIO7 (power), N9 VCCIO7 (power), N18 VCCIO2 (power), N19 VCCIO2 (power), N20 VCCAUX (power), P7 VCCAUX (power), P8 VCCIO6 (power), P9 VCCIO6 (power), P18 VCCIO3 (power), P19 VCCIO3 (power), P20 VCCAUX (power), R7 VCC (power), R8 VCCIO6 (power), R9 VCCIO6 (power), R18 VCCIO3 (power), R19 VCCIO3 (power), R20 VCC (power), T7 VCCAUX (power), T8 VCCAUX (power), T9 VCCIO6 (power), T18 VCCIO3 (power), T19 VCC (power), T20 VCCAUX (power), U6 VCCJ (power), U8 VCC (power), U9 VCCIO6 (power), U18 VCCIO3 (power), U19 VCC (power), V7 VCCAUX (power), V8 VCC (power), V9 VCC (power), V10 VCCIO5 (power), V11 VCCIO5 (power), V12 VCCIO5 (power), V13 VCCIO5 (power), V14 VCCIO4 (power), V15 VCCIO4 (power), V16 VCCIO4 (power), V17 VCCIO4 (power), V18 VCC (power), V19 VCCAUX (power), W8 VCC (power), W9 VCC (power), W10 VCC (power), W11 VCC (power), W12 VCCIO5 (power), W13 VCCIO5 (power), W14 VCCIO4 (power), W15 VCCIO4 (power), W16 VCC (power), W17 VCC (power), W18 VCC (power), W19 VCC (power), W20 VCCAUX (power), Y7 VCCAUX (power), Y13 VCCAUX (power)
part K pins: K10 GND (power), K11 GND (power), K12 GND (power), K13 GND (power), K14 GND (power), K15 GND (power), K16 GND (power), L10 GND (power), L11 GND (power), L12 GND (power), L13 GND (power), L14 GND (power), L15 GND (power), L16 GND (power), L17 GND (power), M10 GND (power), M11 GND (power), M12 GND (power), M13 GND (power), M14 GND (power), M15 GND (power), M16 GND (power), M17 GND (power), N10 GND (power), N11 GND (power), N12 GND (power), N13 GND (power), N14 GND (power), N15 GND (power), N16 GND (power), N17 GND (power), P10 GND (power), P11 GND (power), P12 GND (power), P13 GND (power), P14 GND (power), P15 GND (power), P16 GND (power), P17 GND (power), R10 GND (power), R11 GND (power), R12 GND (power), R13 GND (power), R14 GND (power), R15 GND (power), R16 GND (power), R17 GND (power), T10 GND (power), T11 GND (power), T12 GND (power), T13 GND (power), T14 GND (power), T15 GND (power), T16 GND (power), T17 GND (power), U10 GND (power), U11 GND (power), U12 GND (power), U13 GND (power), U14 GND (power), U15 GND (power), U16 GND (power), U17 GND (power)
part L pins: A25 NC, AA2 NC, AA3 NC, AA4 NC, AA5 NC, AA21 NC, AA22 NC, AA23 NC, AA24 NC, AB3 NC, AB5 NC, AB19 NC, AB20 NC, AB21 NC, AB22 NC, AB23 NC, AB24 NC, AC2 NC, AC3 NC, AC19 NC, AC20 NC, AC21 NC, AC22 NC, AD1 NC, AD2 NC, AD3 NC, AD19 NC, AD20 NC, AD21 NC, AD22 NC, AD23 NC, AD24 NC, AD25 NC, AD26 NC, AE1 NC, AE24 NC, AE25 NC, AE26 NC, AF25 NC, B2 NC, B23 NC, B24 NC, B25 NC, B26 NC, C2 NC, C3 NC, C19 NC, C20 NC, C21 NC, C22 NC, C23 NC, C24 NC, D3 NC, D5 NC, D20 NC, D21 NC, D22 NC, D24 NC, E5 NC, E19 NC, E21 NC, E22 NC, E24 NC, E25 NC, E26 NC, F4 NC, F5 NC, F20 NC, F22 NC, F23 NC, F24 NC, F26 NC, G5 NC, G20 NC, G26 NC, H2 NC, H3 NC, H5 NC, H6 NC, H22 NC, J2 NC, J3 NC, J7 NC, J21 NC, J22 NC, J23 NC, W5 NC, W7 NC, Y5 NC, Y6 NC, Y19 NC, Y20 NC, Y21 NC, Y22 NC, Y23 NC, Y24 NC

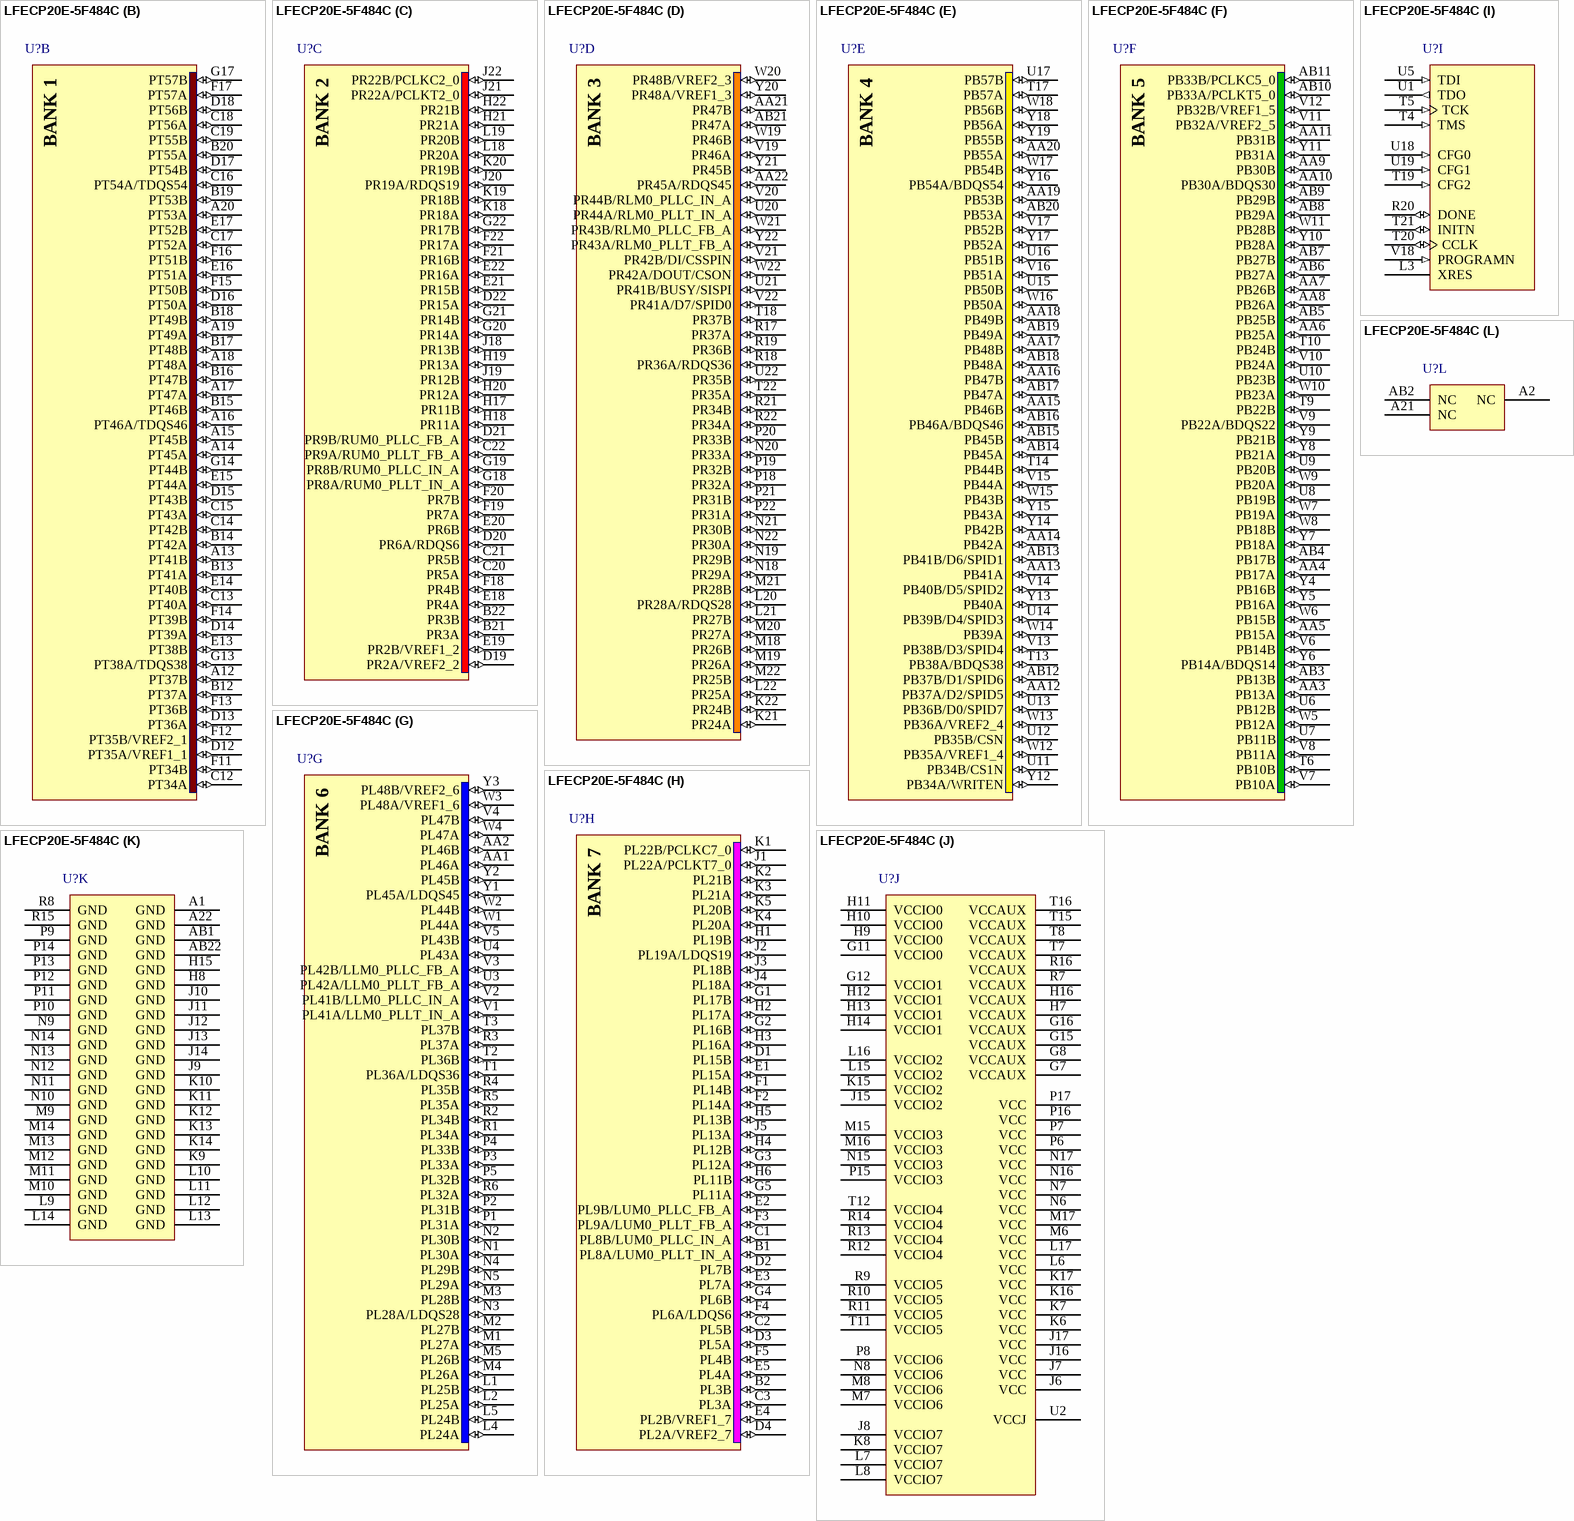
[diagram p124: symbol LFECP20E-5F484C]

## LFECP20E-5F484C
designator U?
ECP 1.2V FPGA, 360 I/Os, 4 PLLs, 19.7K LUTs, 7 sysDSP Blocks, 28 18x18 Multipliers, 484-Pin fpBGA, Speed Grade 5, Commercial Temperature Grade; Note: Pins J6, J17, P6 and P17 are tied to VCCPLL.
footprint fpBGA484 (BGA, 484-Leads, Body 23x23mm, Pitch 1mm)
3D model ECP20E-fpBGA484 (484-Ball Fine Pitch Ball Grid Array (fpBGA484))
part A pins: A3 PT13B (io), A4 PT17B (io), A5 PT25B (io), A6 PT27A (io), A7 PT27B (io), A8 PT29A (io), A9 PT29B (io), A10 PT33A/PCLKT0_0 (io), A11 PT33B/PCLKC0_0 (io), B3 PT13A (io), B4 PT17A (io), B5 PT15A (io), B6 PT25A (io), B7 PT26B (io), B8 PT26A (io), B9 PT30B (io), B10 PT30A/TDQS30 (io), B11 PT31B (io), C4 PT16B (io), C5 PT16A (io), C6 PT14A/TDQS14 (io), C7 PT18A (io), C8 PT21A (io), C9 PT21B (io), C10 PT28A (io), C11 PT31A (io), D5 PT12A (io), D6 PT15B (io), D7 PT19A (io), D8 PT18B (io), D9 PT20A (io), D10 PT23A (io), D11 PT28B (io), E6 PT14B (io), E7 PT10A (io), E8 PT11A (io), E9 PT22A/TDQS22 (io), E10 PT24A (io), E11 PT32A/VREF2_0 (io), E12 PT32B/VREF1_0 (io), F6 PT12B (io), F7 PT11B (io), F8 PT19B (io), F9 PT20B (io), F10 PT23B (io), G6 PT10B (io), G9 PT22B (io), G10 PT24B (io)
part B pins: A12 PT37B (io), A13 PT41B (io), A14 PT45A (io), A15 PT45B (io), A16 PT46A/TDQS46 (io), A17 PT47A (io), A18 PT48A (io), A19 PT49A (io), A20 PT53A (io), B12 PT37A (io), B13 PT41A (io), B14 PT42A (io), B15 PT46B (io), B16 PT47B (io), B17 PT48B (io), B18 PT49B (io), B19 PT53B (io), B20 PT55A (io), C12 PT34A (io), C13 PT40A (io), C14 PT42B (io), C15 PT43A (io), C16 PT54A/TDQS54 (io), C17 PT52A (io), C18 PT56A (io), C19 PT55B (io), D12 PT35A/VREF1_1 (io), D13 PT36A (io), D14 PT39A (io), D15 PT43B (io), D16 PT50A (io), D17 PT54B (io), D18 PT56B (io), E13 PT38B (io), E14 PT40B (io), E15 PT44A (io), E16 PT51A (io), E17 PT52B (io), F11 PT34B (io), F12 PT35B/VREF2_1 (io), F13 PT36B (io), F14 PT39B (io), F15 PT50B (io), F16 PT51B (io), F17 PT57A (io), G13 PT38A/TDQS38 (io), G14 PT44B (io), G17 PT57B (io)
part C pins: B21 PR3A (io), B22 PR3B (io), C20 PR5A (io), C21 PR5B (io), C22 PR9A/RUM0_PLLT_FB_A (io), D19 PR2A/VREF2_2 (io), D20 PR6A/RDQS6 (io), D21 PR9B/RUM0_PLLC_FB_A (io), D22 PR15A (io), E18 PR4A (io), E19 PR2B/VREF1_2 (io), E20 PR6B (io), E21 PR15B (io), E22 PR16A (io), F18 PR4B (io), F19 PR7A (io), F20 PR7B (io), F21 PR16B (io), F22 PR17A (io), G18 PR8A/RUM0_PLLT_IN_A (io), G19 PR8B/RUM0_PLLC_IN_A (io), G20 PR14A (io), G21 PR14B (io), G22 PR17B (io), H17 PR11B (io), H18 PR11A (io), H19 PR13A (io), H20 PR12A (io), H21 PR21A (io), H22 PR21B (io), J18 PR13B (io), J19 PR12B (io), J20 PR19A/RDQS19 (io), J21 PR22A/PCLKT2_0 (io), J22 PR22B/PCLKC2_0 (io), K18 PR18A (io), K19 PR18B (io), K20 PR19B (io), L18 PR20A (io), L19 PR20B (io)
part D pins: AA21 PR47B (io), AA22 PR45A/RDQS45 (io), AB21 PR47A (io), K21 PR24A (io), K22 PR24B (io), L20 PR28A/RDQS28 (io), L21 PR27B (io), L22 PR25A (io), M18 PR26B (io), M19 PR26A (io), M20 PR27A (io), M21 PR28B (io), M22 PR25B (io), N18 PR29A (io), N19 PR29B (io), N20 PR33A (io), N21 PR30B (io), N22 PR30A (io), P18 PR32A (io), P19 PR32B (io), P20 PR33B (io), P21 PR31B (io), P22 PR31A (io), R17 PR37A (io), R18 PR36A/RDQS36 (io), R19 PR36B (io), R21 PR34B (io), R22 PR34A (io), T18 PR37B (io), T22 PR35A (io), U20 PR44A/RLM0_PLLT_IN_A (io), U21 PR41B/BUSY/SISPI (io), U22 PR35B (io), V19 PR46A (io), V20 PR44B/RLM0_PLLC_IN_A (io), V21 PR42B/DI/CSSPIN (io), V22 PR41A/D7/SPID0 (io), W19 PR46B (io), W20 PR48B/VREF2_3 (io), W21 PR43B/RLM0_PLLC_FB_A (io), W22 PR42A/DOUT/CSON (io), Y20 PR48A/VREF1_3 (io), Y21 PR45B (io), Y22 PR43A/RLM0_PLLT_FB_A (io)
part E pins: AA12 PB37A/D2/SPID5 (io), AA13 PB41A (io), AA14 PB42A (io), AA15 PB46B (io), AA16 PB47B (io), AA17 PB48B (io), AA18 PB49B (io), AA19 PB53B (io), AA20 PB55A (io), AB12 PB37B/D1/SPID6 (io), AB13 PB41B/D6/SPID1 (io), AB14 PB45A (io), AB15 PB45B (io), AB16 PB46A/BDQS46 (io), AB17 PB47A (io), AB18 PB48A (io), AB19 PB49A (io), AB20 PB53A (io), T13 PB38A/BDQS38 (io), T14 PB44B (io), T17 PB57A (io), U11 PB34B/CS1N (io), U12 PB35B/CSN (io), U13 PB36B/D0/SPID7 (io), U14 PB39B/D4/SPID3 (io), U15 PB50B (io), U16 PB51B (io), U17 PB57B (io), V13 PB38B/D3/SPID4 (io), V14 PB40B/D5/SPID2 (io), V15 PB44A (io), V16 PB51A (io), V17 PB52B (io), W12 PB35A/VREF1_4 (io), W13 PB36A/VREF2_4 (io), W14 PB39A (io), W15 PB43B (io), W16 PB50A (io), W17 PB54B (io), W18 PB56B (io), Y12 PB34A/WRITEN (io), Y13 PB40A (io), Y14 PB42B (io), Y15 PB43A (io), Y16 PB54A/BDQS54 (io), Y17 PB52A (io), Y18 PB56A (io), Y19 PB55B (io)
part F pins: AA3 PB13A (io), AA4 PB17A (io), AA5 PB15A (io), AA6 PB25A (io), AA7 PB26B (io), AA8 PB26A (io), AA9 PB30B (io), AA10 PB30A/BDQS30 (io), AA11 PB31B (io), AB3 PB13B (io), AB4 PB17B (io), AB5 PB25B (io), AB6 PB27A (io), AB7 PB27B (io), AB8 PB29A (io), AB9 PB29B (io), AB10 PB33A/PCLKT5_0 (io), AB11 PB33B/PCLKC5_0 (io), T6 PB10B (io), T9 PB22B (io), T10 PB24B (io), U6 PB12B (io), U7 PB11B (io), U8 PB19B (io), U9 PB20B (io), U10 PB23B (io), V6 PB14B (io), V7 PB10A (io), V8 PB11A (io), V9 PB22A/BDQS22 (io), V10 PB24A (io), V11 PB32A/VREF2_5 (io), V12 PB32B/VREF1_5 (io), W5 PB12A (io), W6 PB15B (io), W7 PB19A (io), W8 PB18B (io), W9 PB20A (io), W10 PB23A (io), W11 PB28B (io), Y4 PB16B (io), Y5 PB16A (io), Y6 PB14A/BDQS14 (io), Y7 PB18A (io), Y8 PB21A (io), Y9 PB21B (io), Y10 PB28A (io), Y11 PB31A (io)
part G pins: AA1 PL46A (io), AA2 PL46B (io), L1 PL25B (io), L2 PL25A (io), L4 PL24A (io), L5 PL24B (io), M1 PL27A (io), M2 PL27B (io), M3 PL28B (io), M4 PL26A (io), M5 PL26B (io), N1 PL30A (io), N2 PL30B (io), N3 PL28A/LDQS28 (io), N4 PL29B (io), N5 PL29A (io), P1 PL31A (io), P2 PL31B (io), P3 PL33A (io), P4 PL33B (io), P5 PL32B (io), R1 PL34A (io), R2 PL34B (io), R3 PL37A (io), R4 PL35B (io), R5 PL35A (io), R6 PL32A (io), T1 PL36A/LDQS36 (io), T2 PL36B (io), T3 PL37B (io), U3 PL42A/LLM0_PLLT_FB_A (io), U4 PL43A (io), V1 PL41A/LLM0_PLLT_IN_A (io), V2 PL41B/LLM0_PLLC_IN_A (io), V3 PL42B/LLM0_PLLC_FB_A (io), V4 PL47B (io), V5 PL43B (io), W1 PL44A (io), W2 PL44B (io), W3 PL48A/VREF1_6 (io), W4 PL47A (io), Y1 PL45A/LDQS45 (io), Y2 PL45B (io), Y3 PL48B/VREF2_6 (io)
part H pins: B1 PL8A/LUM0_PLLT_IN_A (io), B2 PL3B (io), C1 PL8B/LUM0_PLLC_IN_A (io), C2 PL5B (io), C3 PL3A (io), D1 PL15B (io), D2 PL7B (io), D3 PL5A (io), D4 PL2A/VREF2_7 (io), E1 PL15A (io), E2 PL9B/LUM0_PLLC_FB_A (io), E3 PL7A (io), E4 PL2B/VREF1_7 (io), E5 PL4A (io), F1 PL14B (io), F2 PL14A (io), F3 PL9A/LUM0_PLLT_FB_A (io), F4 PL6A/LDQS6 (io), F5 PL4B (io), G1 PL17B (io), G2 PL16B (io), G3 PL12A (io), G4 PL6B (io), G5 PL11A (io), H1 PL19B (io), H2 PL17A (io), H3 PL16A (io), H4 PL12B (io), H5 PL13B (io), H6 PL11B (io), J1 PL22A/PCLKT7_0 (io), J2 PL19A/LDQS19 (io), J3 PL18B (io), J4 PL18A (io), J5 PL13A (io), K1 PL22B/PCLKC7_0 (io), K2 PL21B (io), K3 PL21A (io), K4 PL20A (io), K5 PL20B (io)
part I pins: L3 XRES, R20 DONE (io), T4 TMS (in), T5 TCK (in), T19 CFG2 (in), T20 CCLK (io), T21 INITN (io), U1 TDO (out), U5 TDI (in), U18 CFG0 (in), U19 CFG1 (in), V18 PROGRAMN (in)
part J pins: G7 VCCAUX (power), G8 VCCAUX (power), G11 VCCIO0 (power), G12 VCCIO1 (power), G15 VCCAUX (power), G16 VCCAUX (power), H7 VCCAUX (power), H9 VCCIO0 (power), H10 VCCIO0 (power), H11 VCCIO0 (power), H12 VCCIO1 (power), H13 VCCIO1 (power), H14 VCCIO1 (power), H16 VCCAUX (power), J6 VCC (power), J7 VCC (power), J8 VCCIO7 (power), J15 VCCIO2 (power), J16 VCC (power), J17 VCC (power), K6 VCC (power), K7 VCC (power), K8 VCCIO7 (power), K15 VCCIO2 (power), K16 VCC (power), K17 VCC (power), L6 VCC (power), L7 VCCIO7 (power), L8 VCCIO7 (power), L15 VCCIO2 (power), L16 VCCIO2 (power), L17 VCC (power), M6 VCC (power), M7 VCCIO6 (power), M8 VCCIO6 (power), M15 VCCIO3 (power), M16 VCCIO3 (power), M17 VCC (power), N6 VCC (power), N7 VCC (power), N8 VCCIO6 (power), N15 VCCIO3 (power), N16 VCC (power), N17 VCC (power), P6 VCC (power), P7 VCC (power), P8 VCCIO6 (power), P15 VCCIO3 (power), P16 VCC (power), P17 VCC (power), R7 VCCAUX (power), R9 VCCIO5 (power), R10 VCCIO5 (power), R11 VCCIO5 (power), R12 VCCIO4 (power), R13 VCCIO4 (power), R14 VCCIO4 (power), R16 VCCAUX (power), T7 VCCAUX (power), T8 VCCAUX (power), T11 VCCIO5 (power), T12 VCCIO4 (power), T15 VCCAUX (power), T16 VCCAUX (power), U2 VCCJ (power)
part K pins: A1 GND (power), A22 GND (power), AB1 GND (power), AB22 GND (power), H8 GND (power), H15 GND (power), J9 GND (power), J10 GND (power), J11 GND (power), J12 GND (power), J13 GND (power), J14 GND (power), K9 GND (power), K10 GND (power), K11 GND (power), K12 GND (power), K13 GND (power), K14 GND (power), L9 GND (power), L10 GND (power), L11 GND (power), L12 GND (power), L13 GND (power), L14 GND (power), M9 GND (power), M10 GND (power), M11 GND (power), M12 GND (power), M13 GND (power), M14 GND (power), N9 GND (power), N10 GND (power), N11 GND (power), N12 GND (power), N13 GND (power), N14 GND (power), P9 GND (power), P10 GND (power), P11 GND (power), P12 GND (power), P13 GND (power), P14 GND (power), R8 GND (power), R15 GND (power)
part L pins: A2 NC, A21 NC, AB2 NC

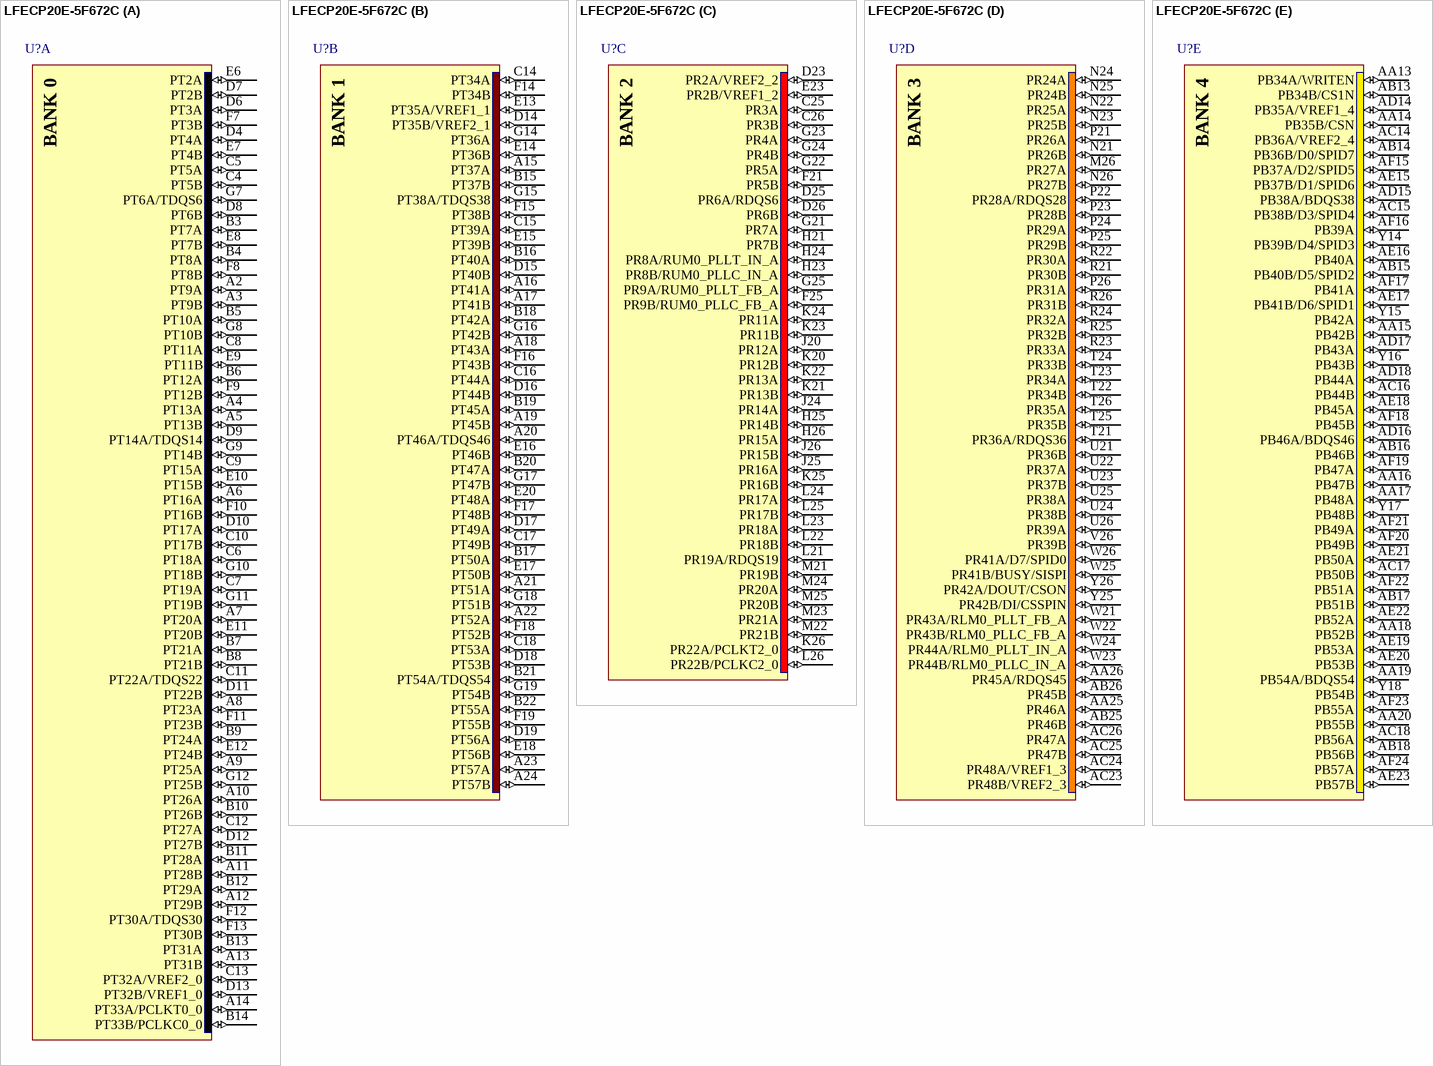
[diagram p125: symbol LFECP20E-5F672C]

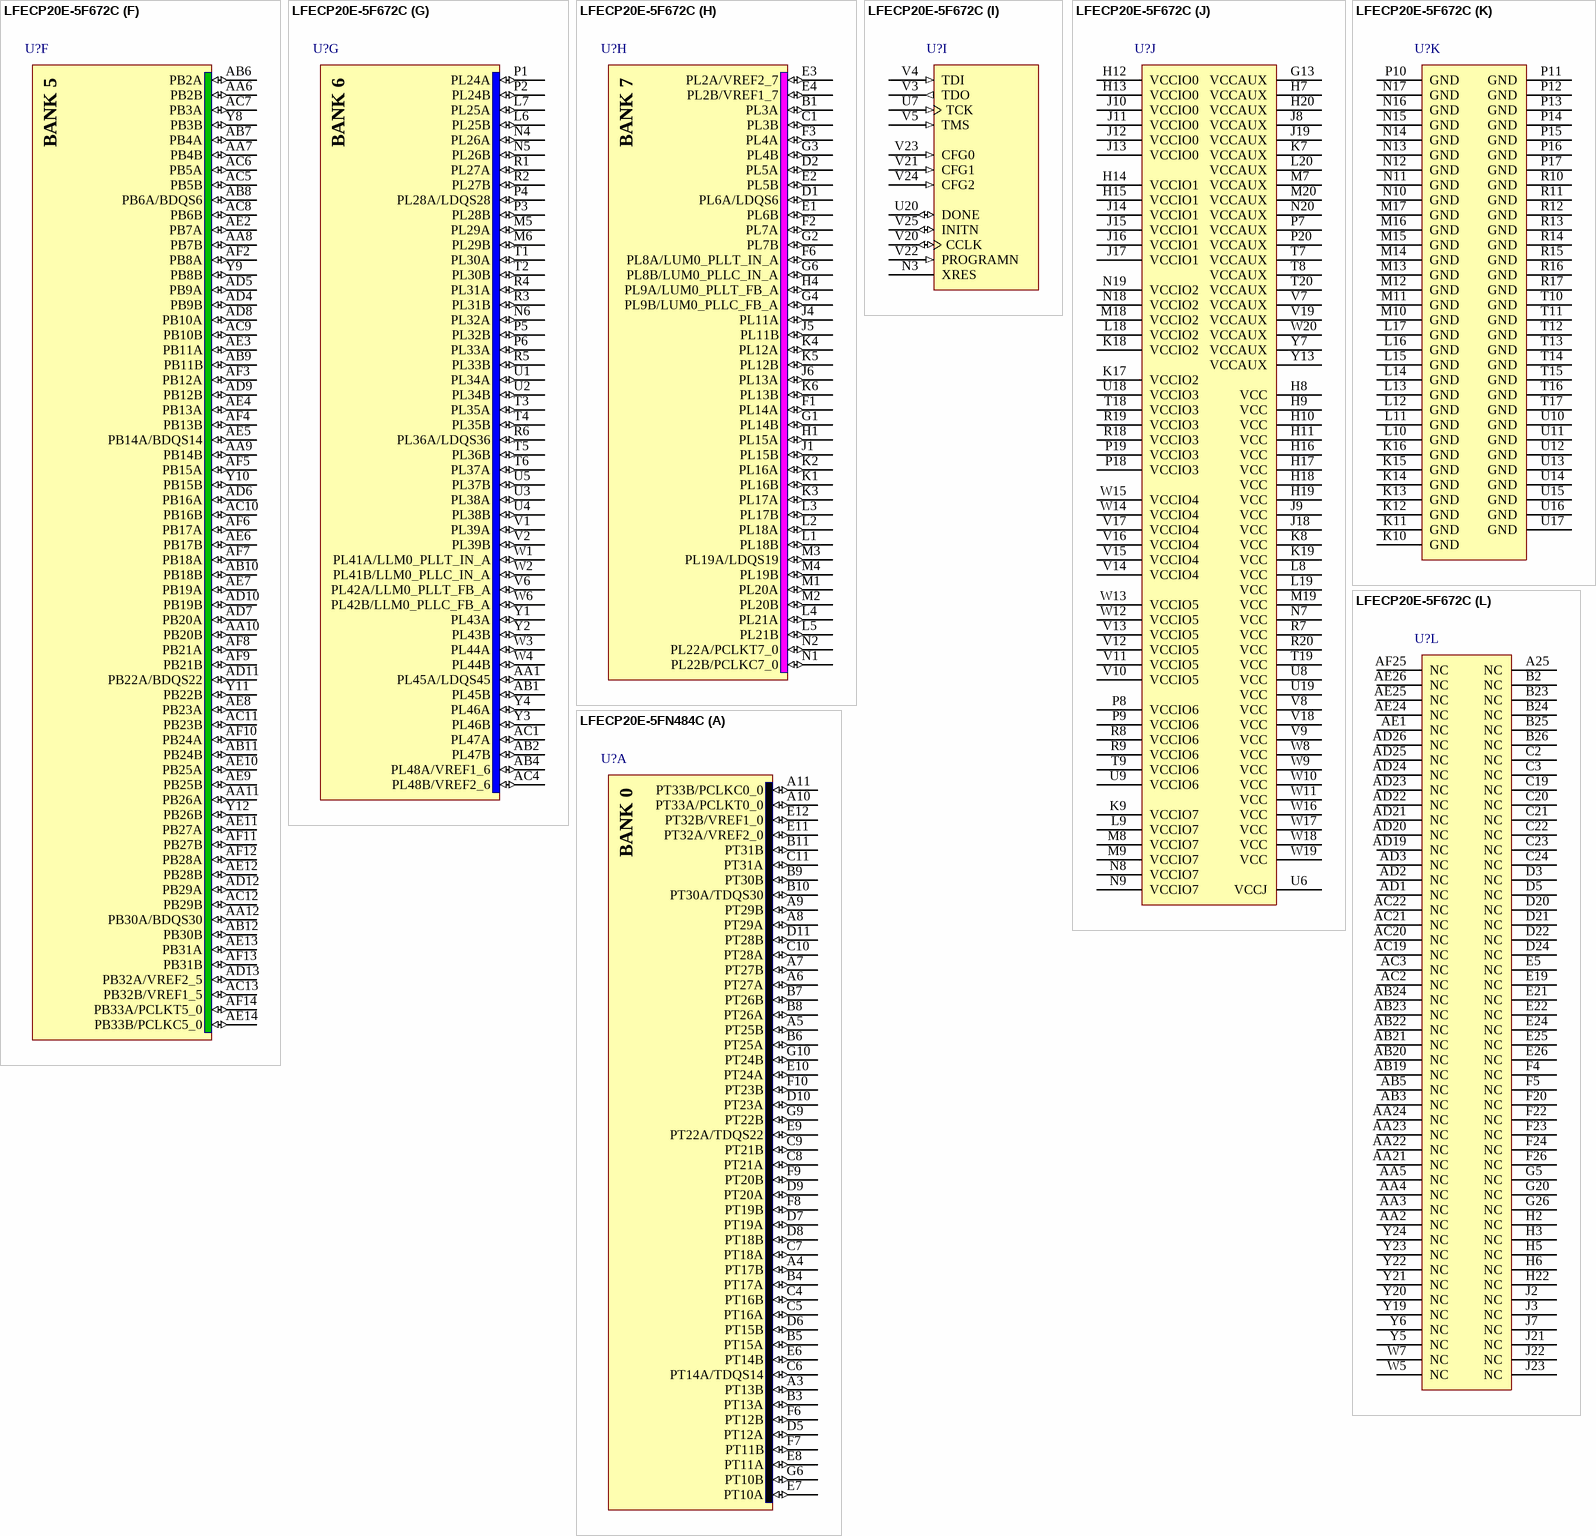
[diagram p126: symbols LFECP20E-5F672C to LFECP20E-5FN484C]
